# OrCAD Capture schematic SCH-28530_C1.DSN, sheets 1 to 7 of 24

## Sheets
1 01 Cover Page: title: X-T1023RDB-PC; rev: C1; company: Freescale Semiconductor; note: SCH-28530 PDF: SPF-28530; note: 6501 William Cannon Drive West; note: Austin, TX 78735-8598
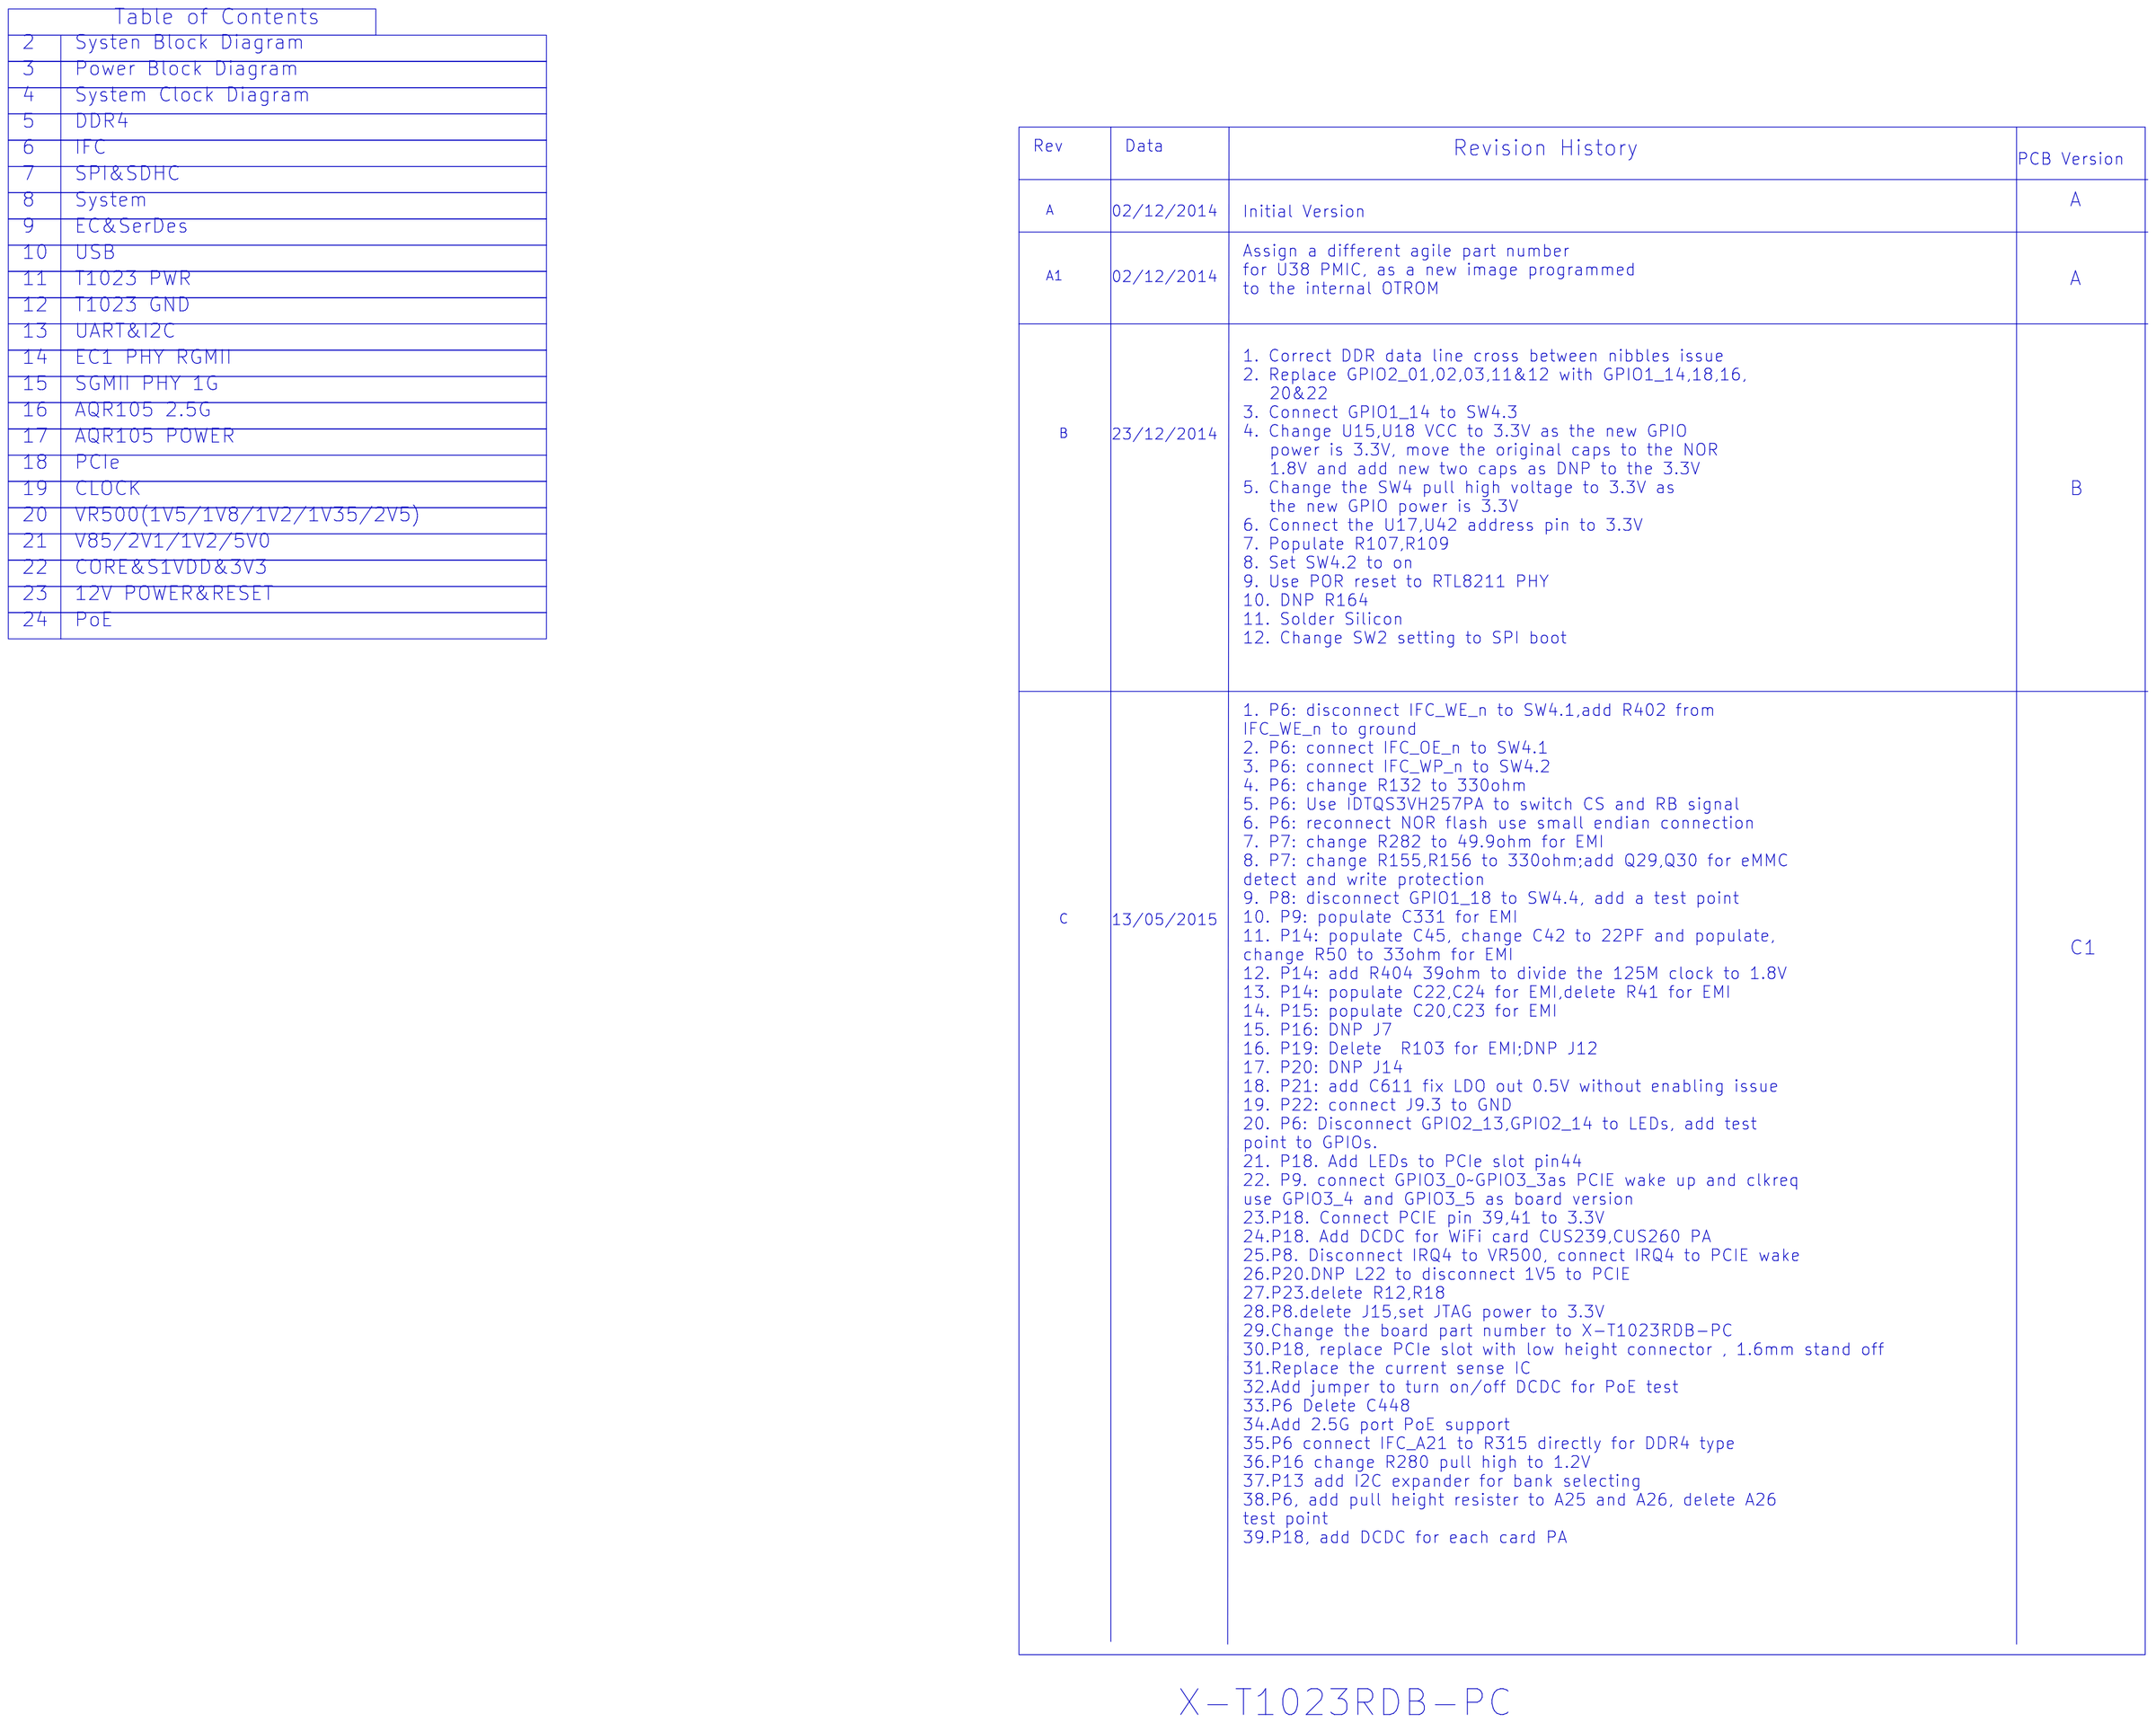
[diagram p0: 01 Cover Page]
2 02 System Block Diagram
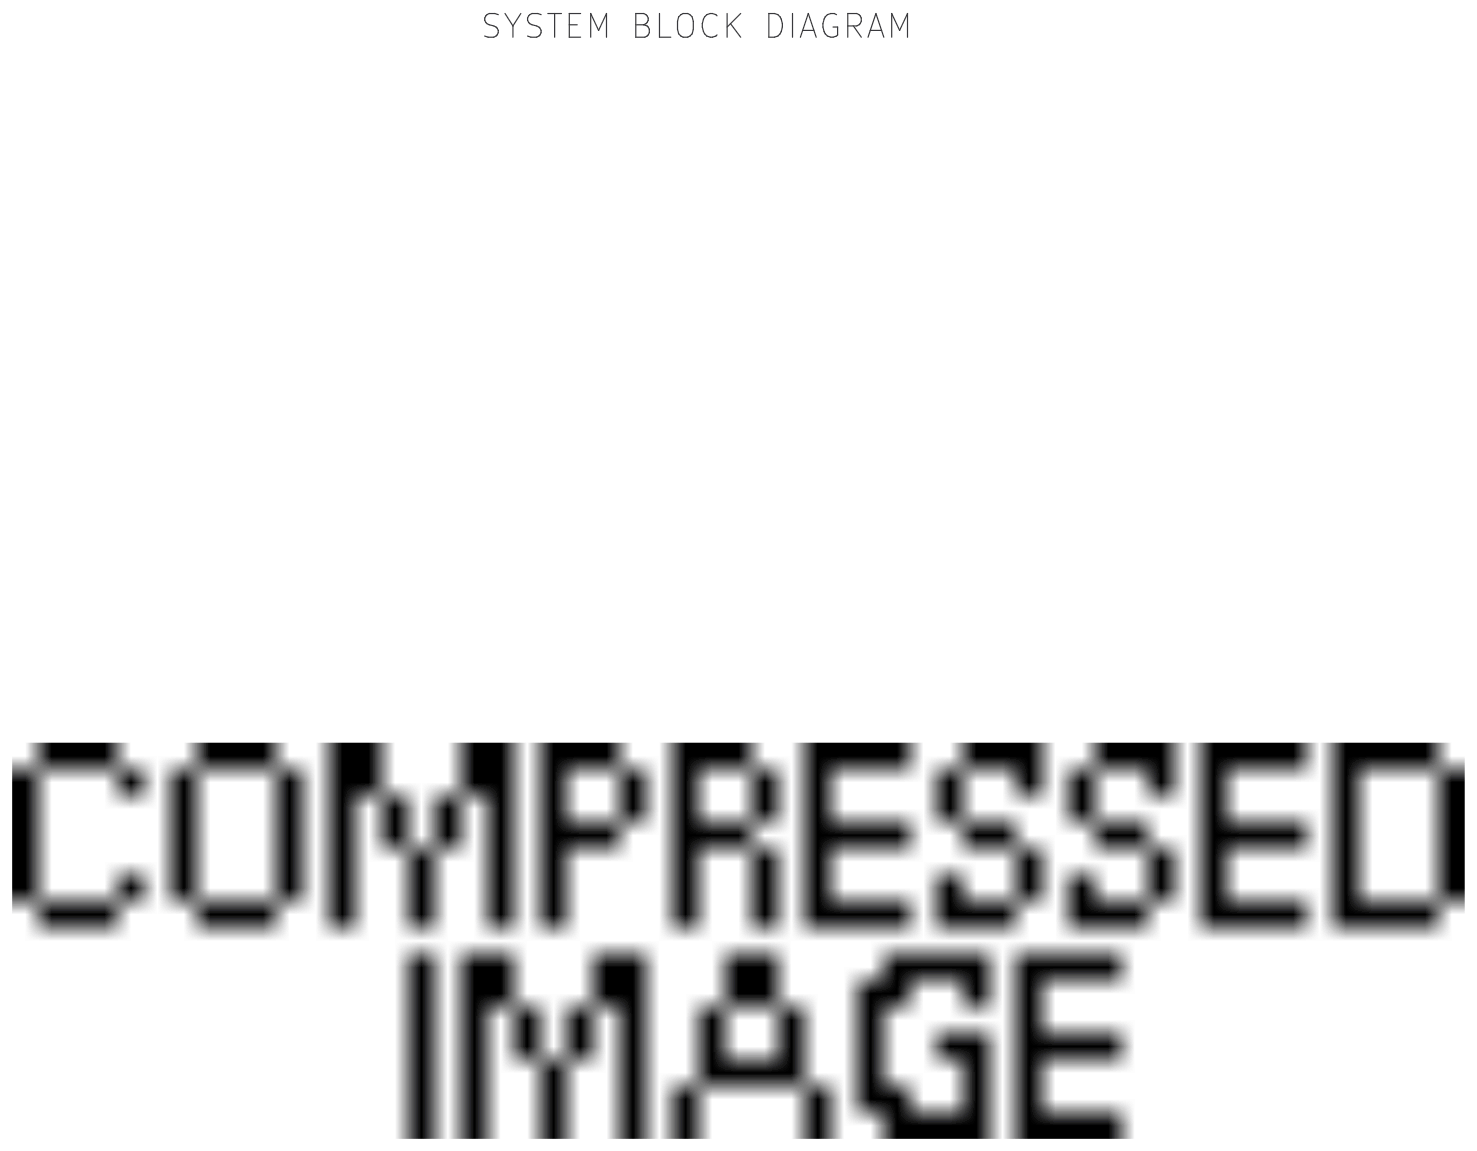
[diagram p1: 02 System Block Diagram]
3 03 Power Block Diagram
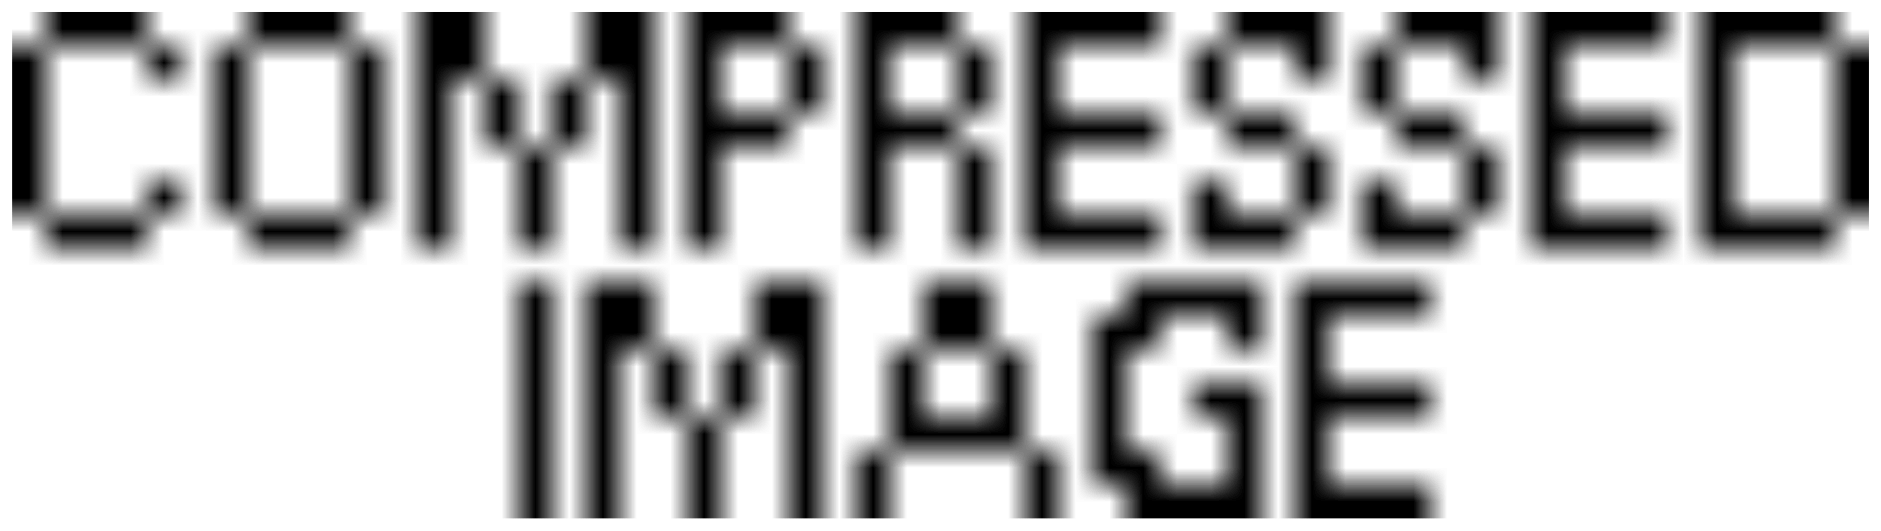
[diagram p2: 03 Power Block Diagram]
4 04 Clock Block Diagram
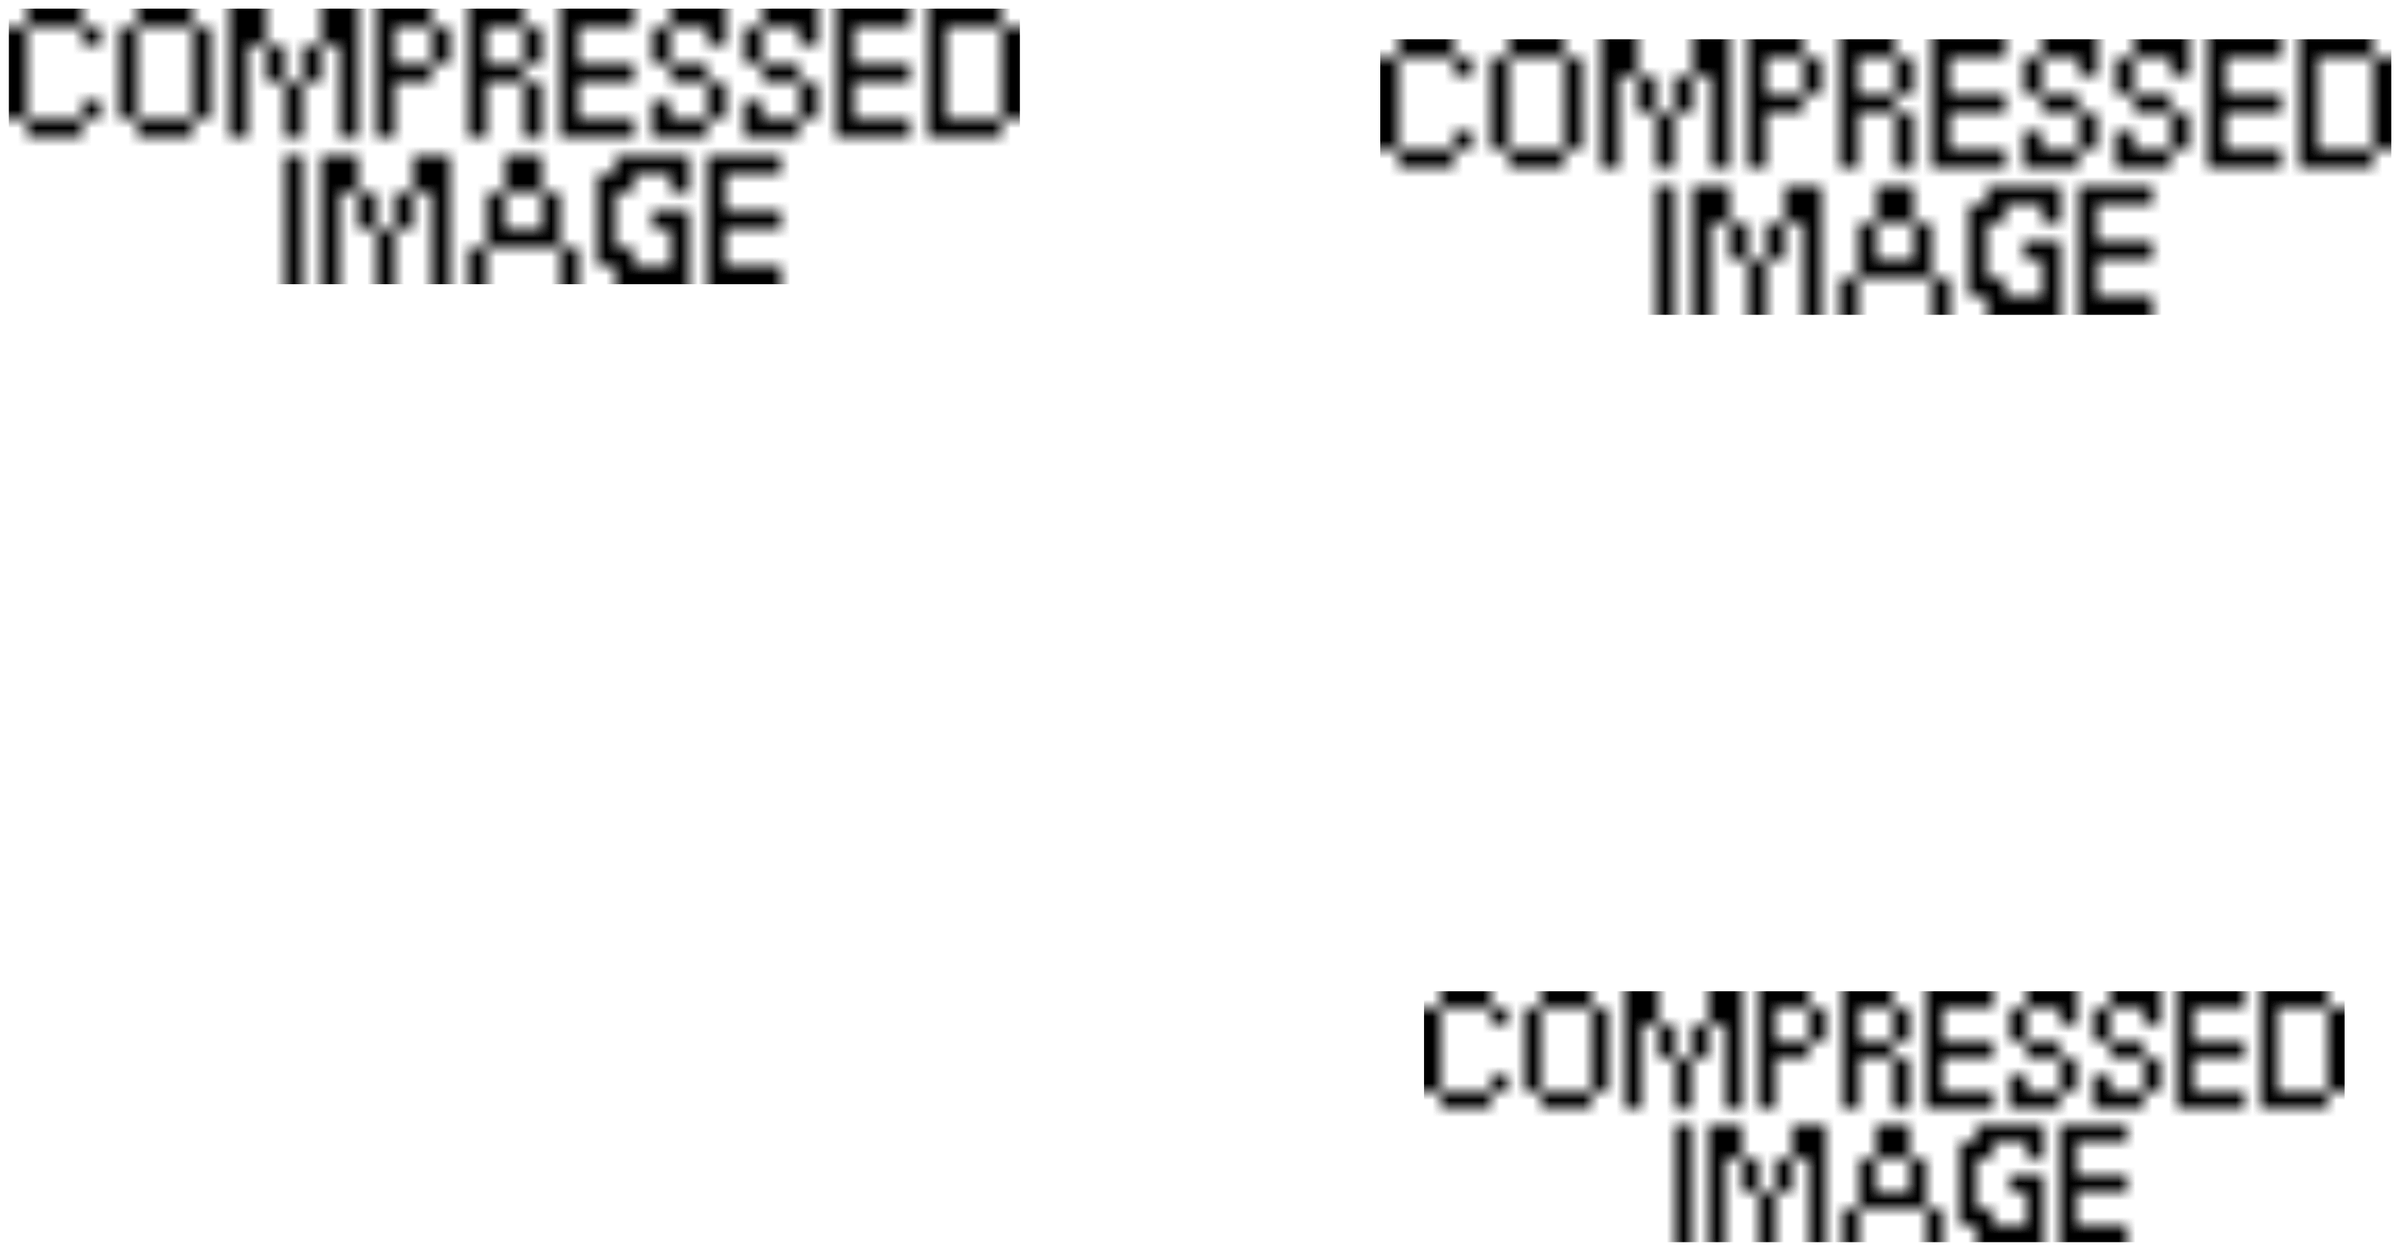
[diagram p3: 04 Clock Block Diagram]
5 05 DDR4: size C
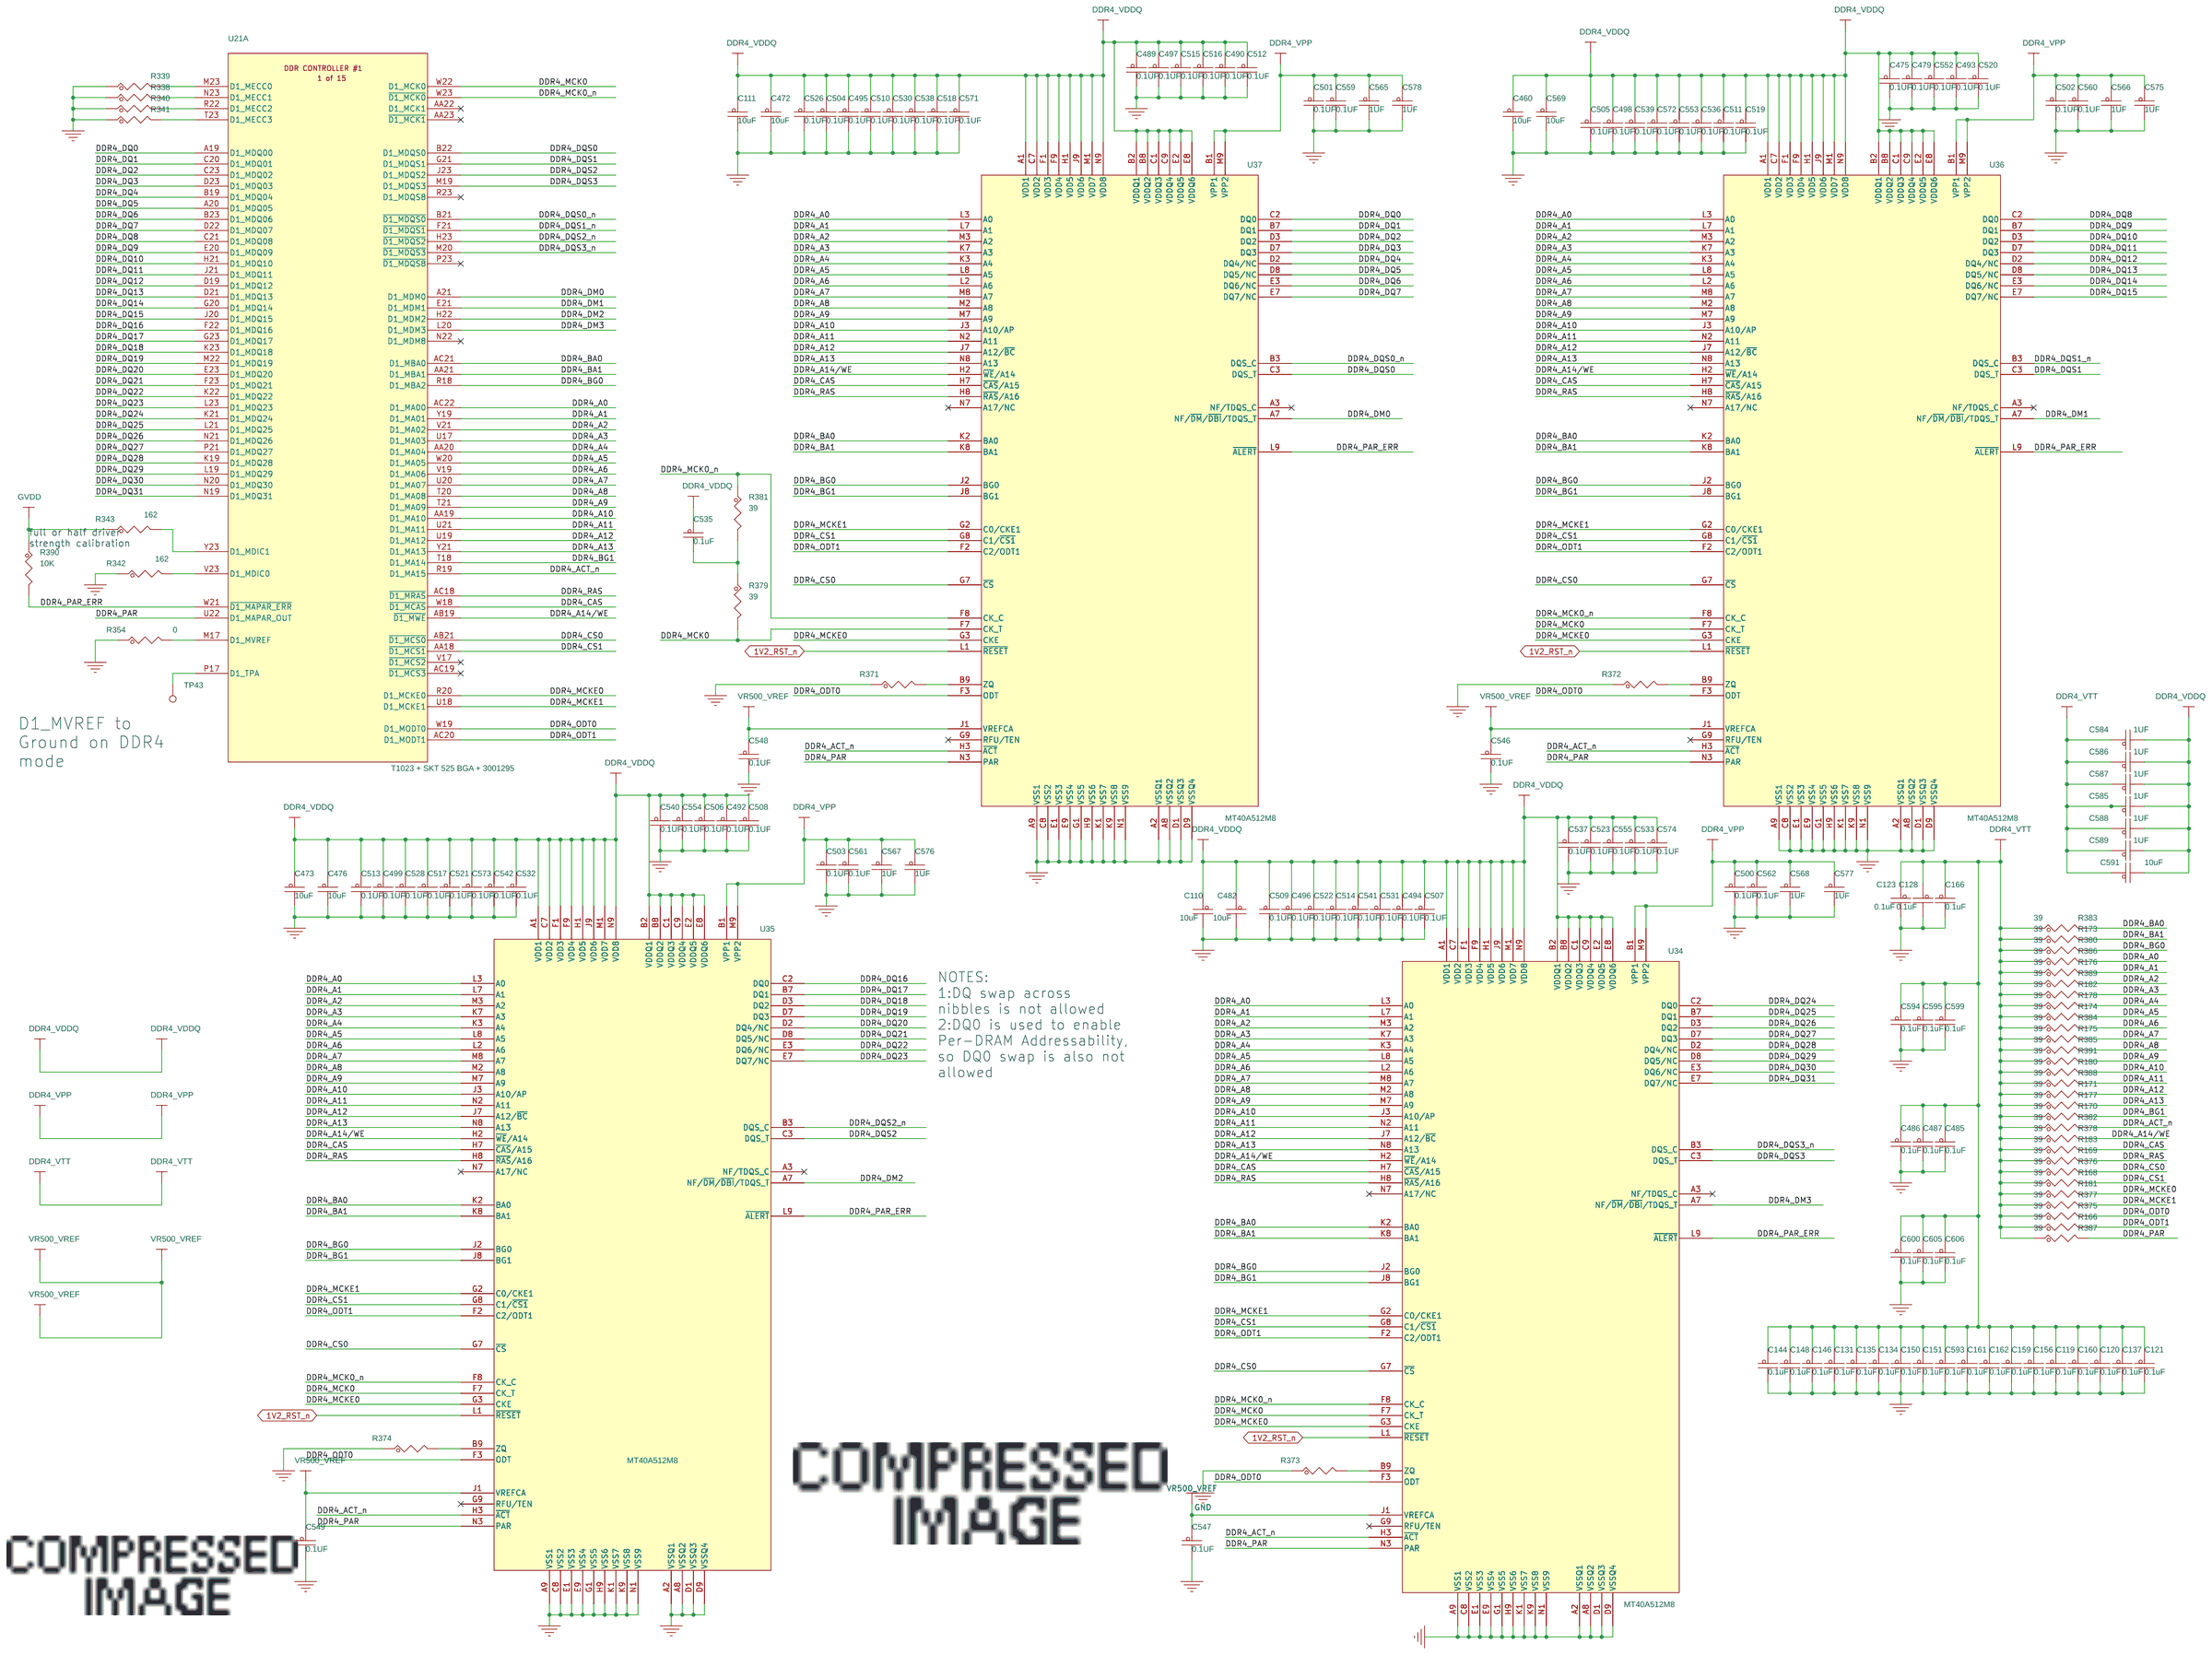
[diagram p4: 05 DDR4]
6 06 IFC: size C
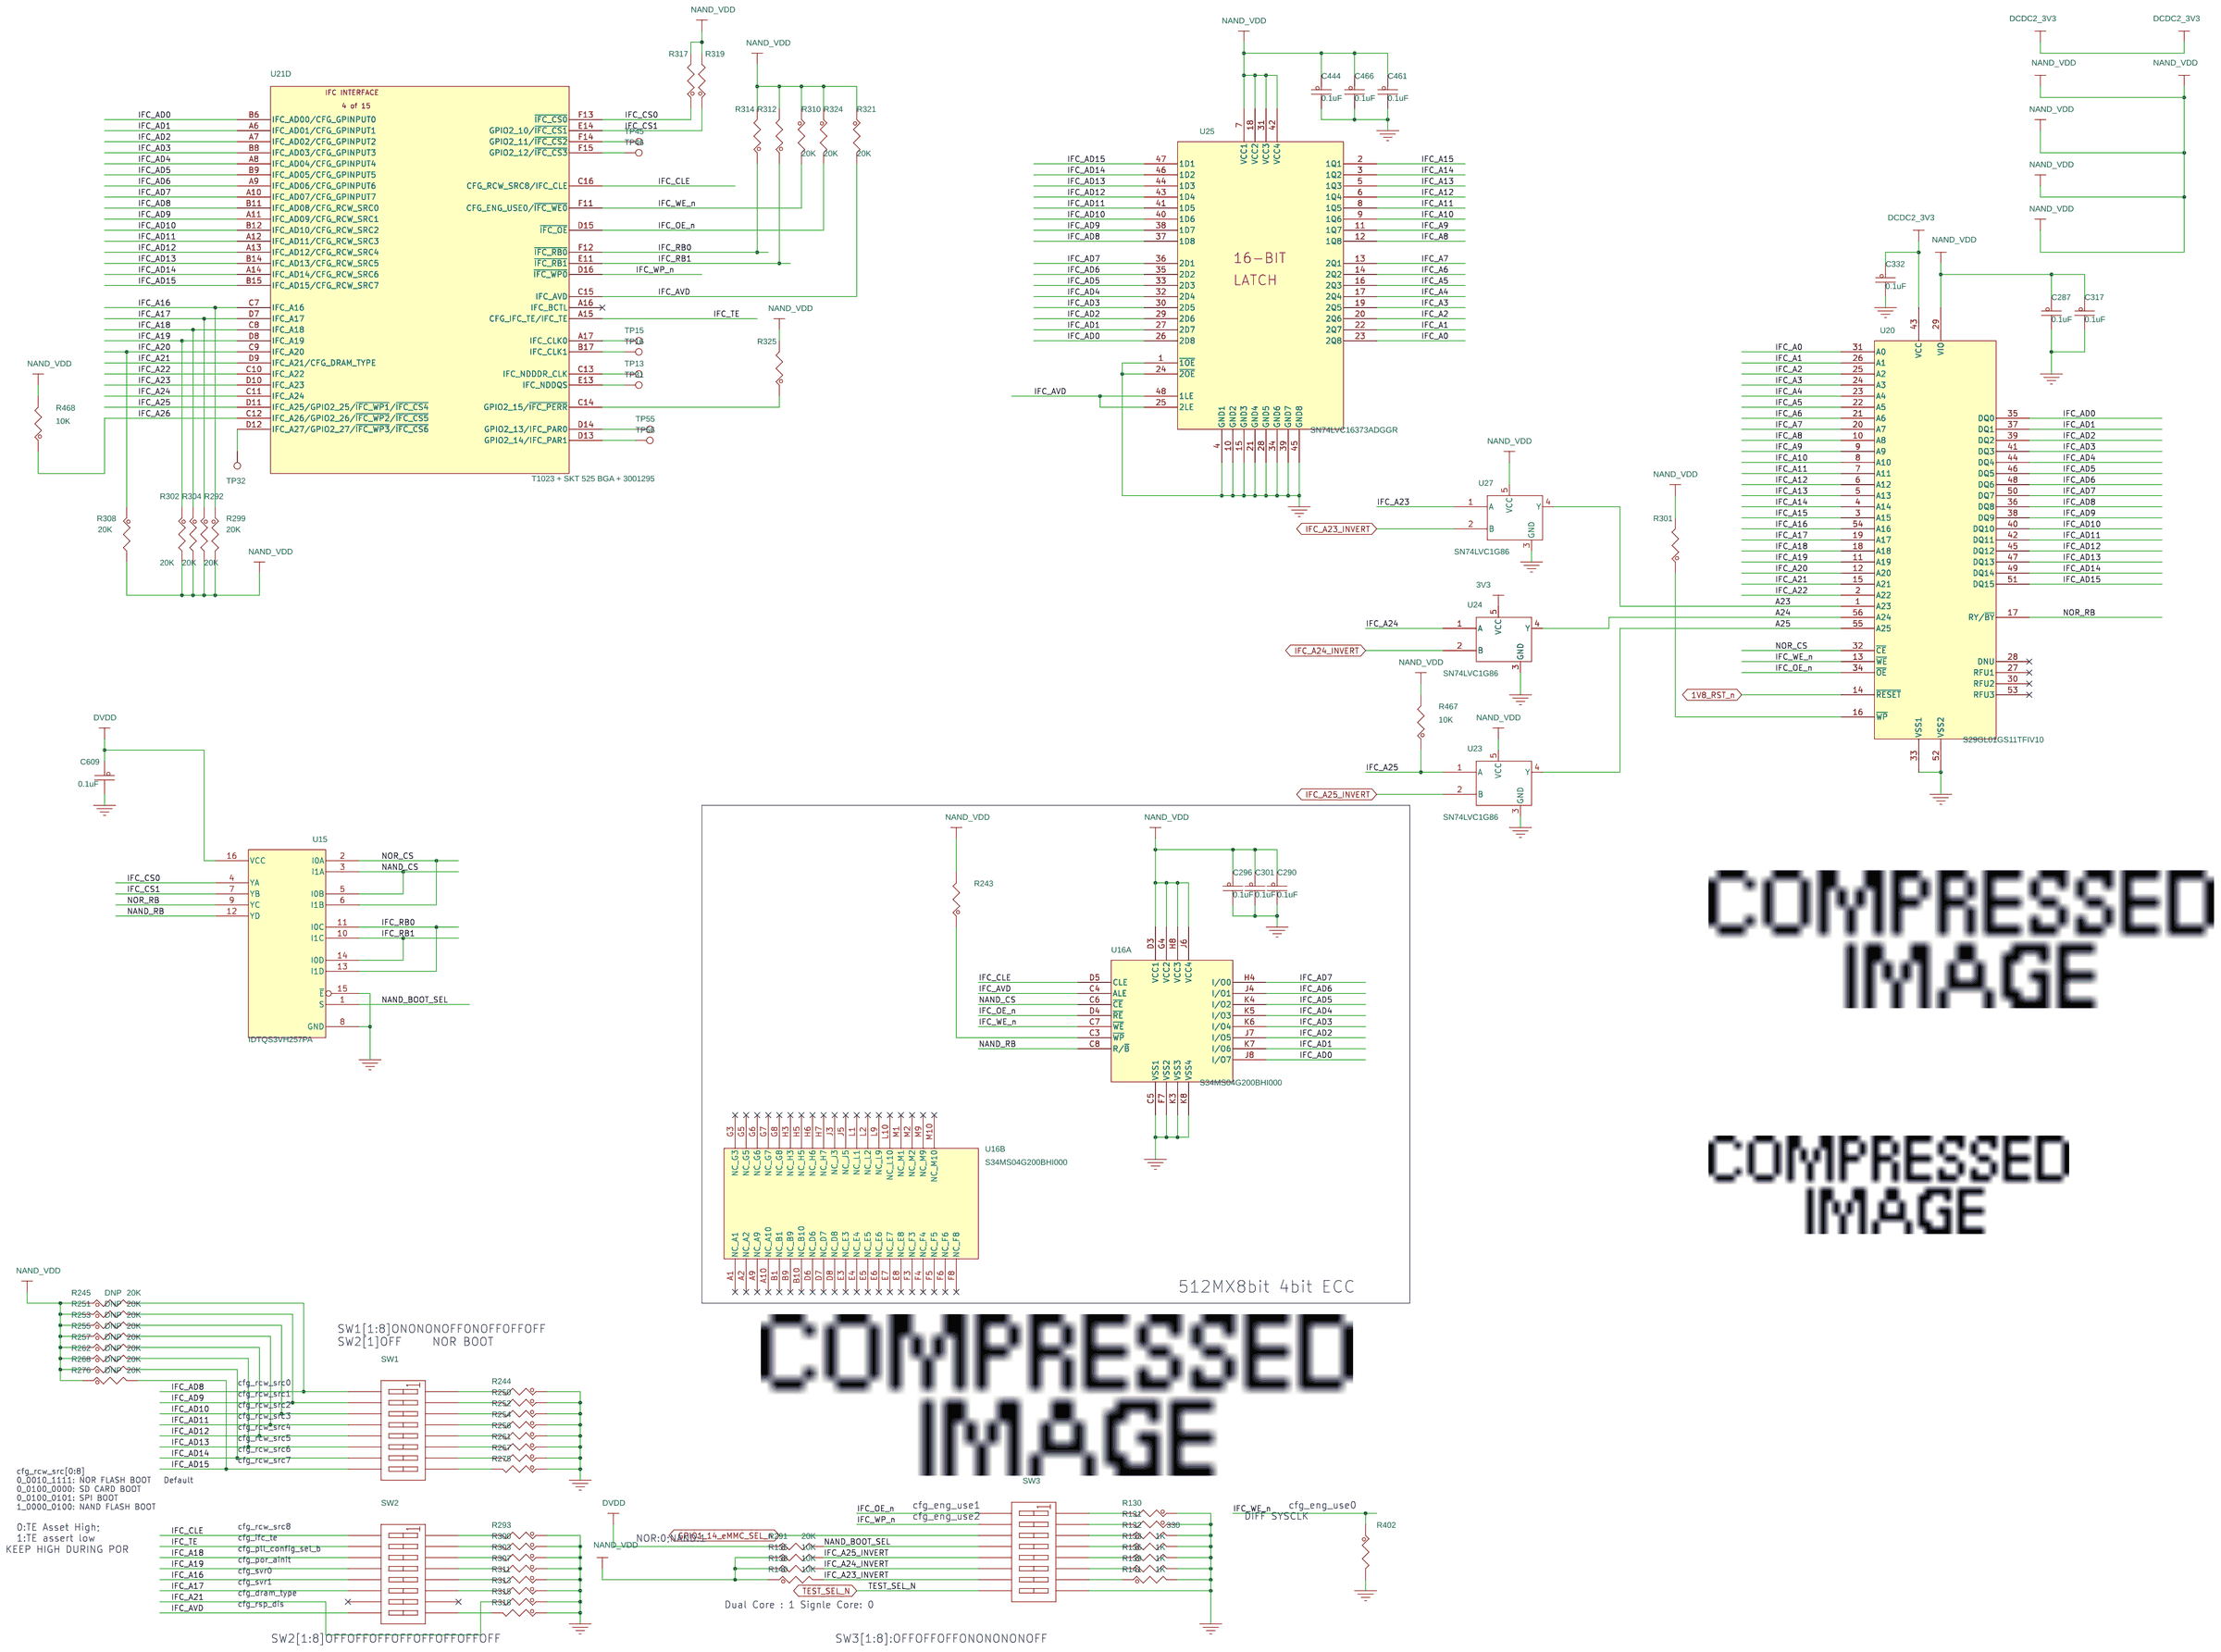
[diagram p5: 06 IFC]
7 07 SPI&SDHC: size C
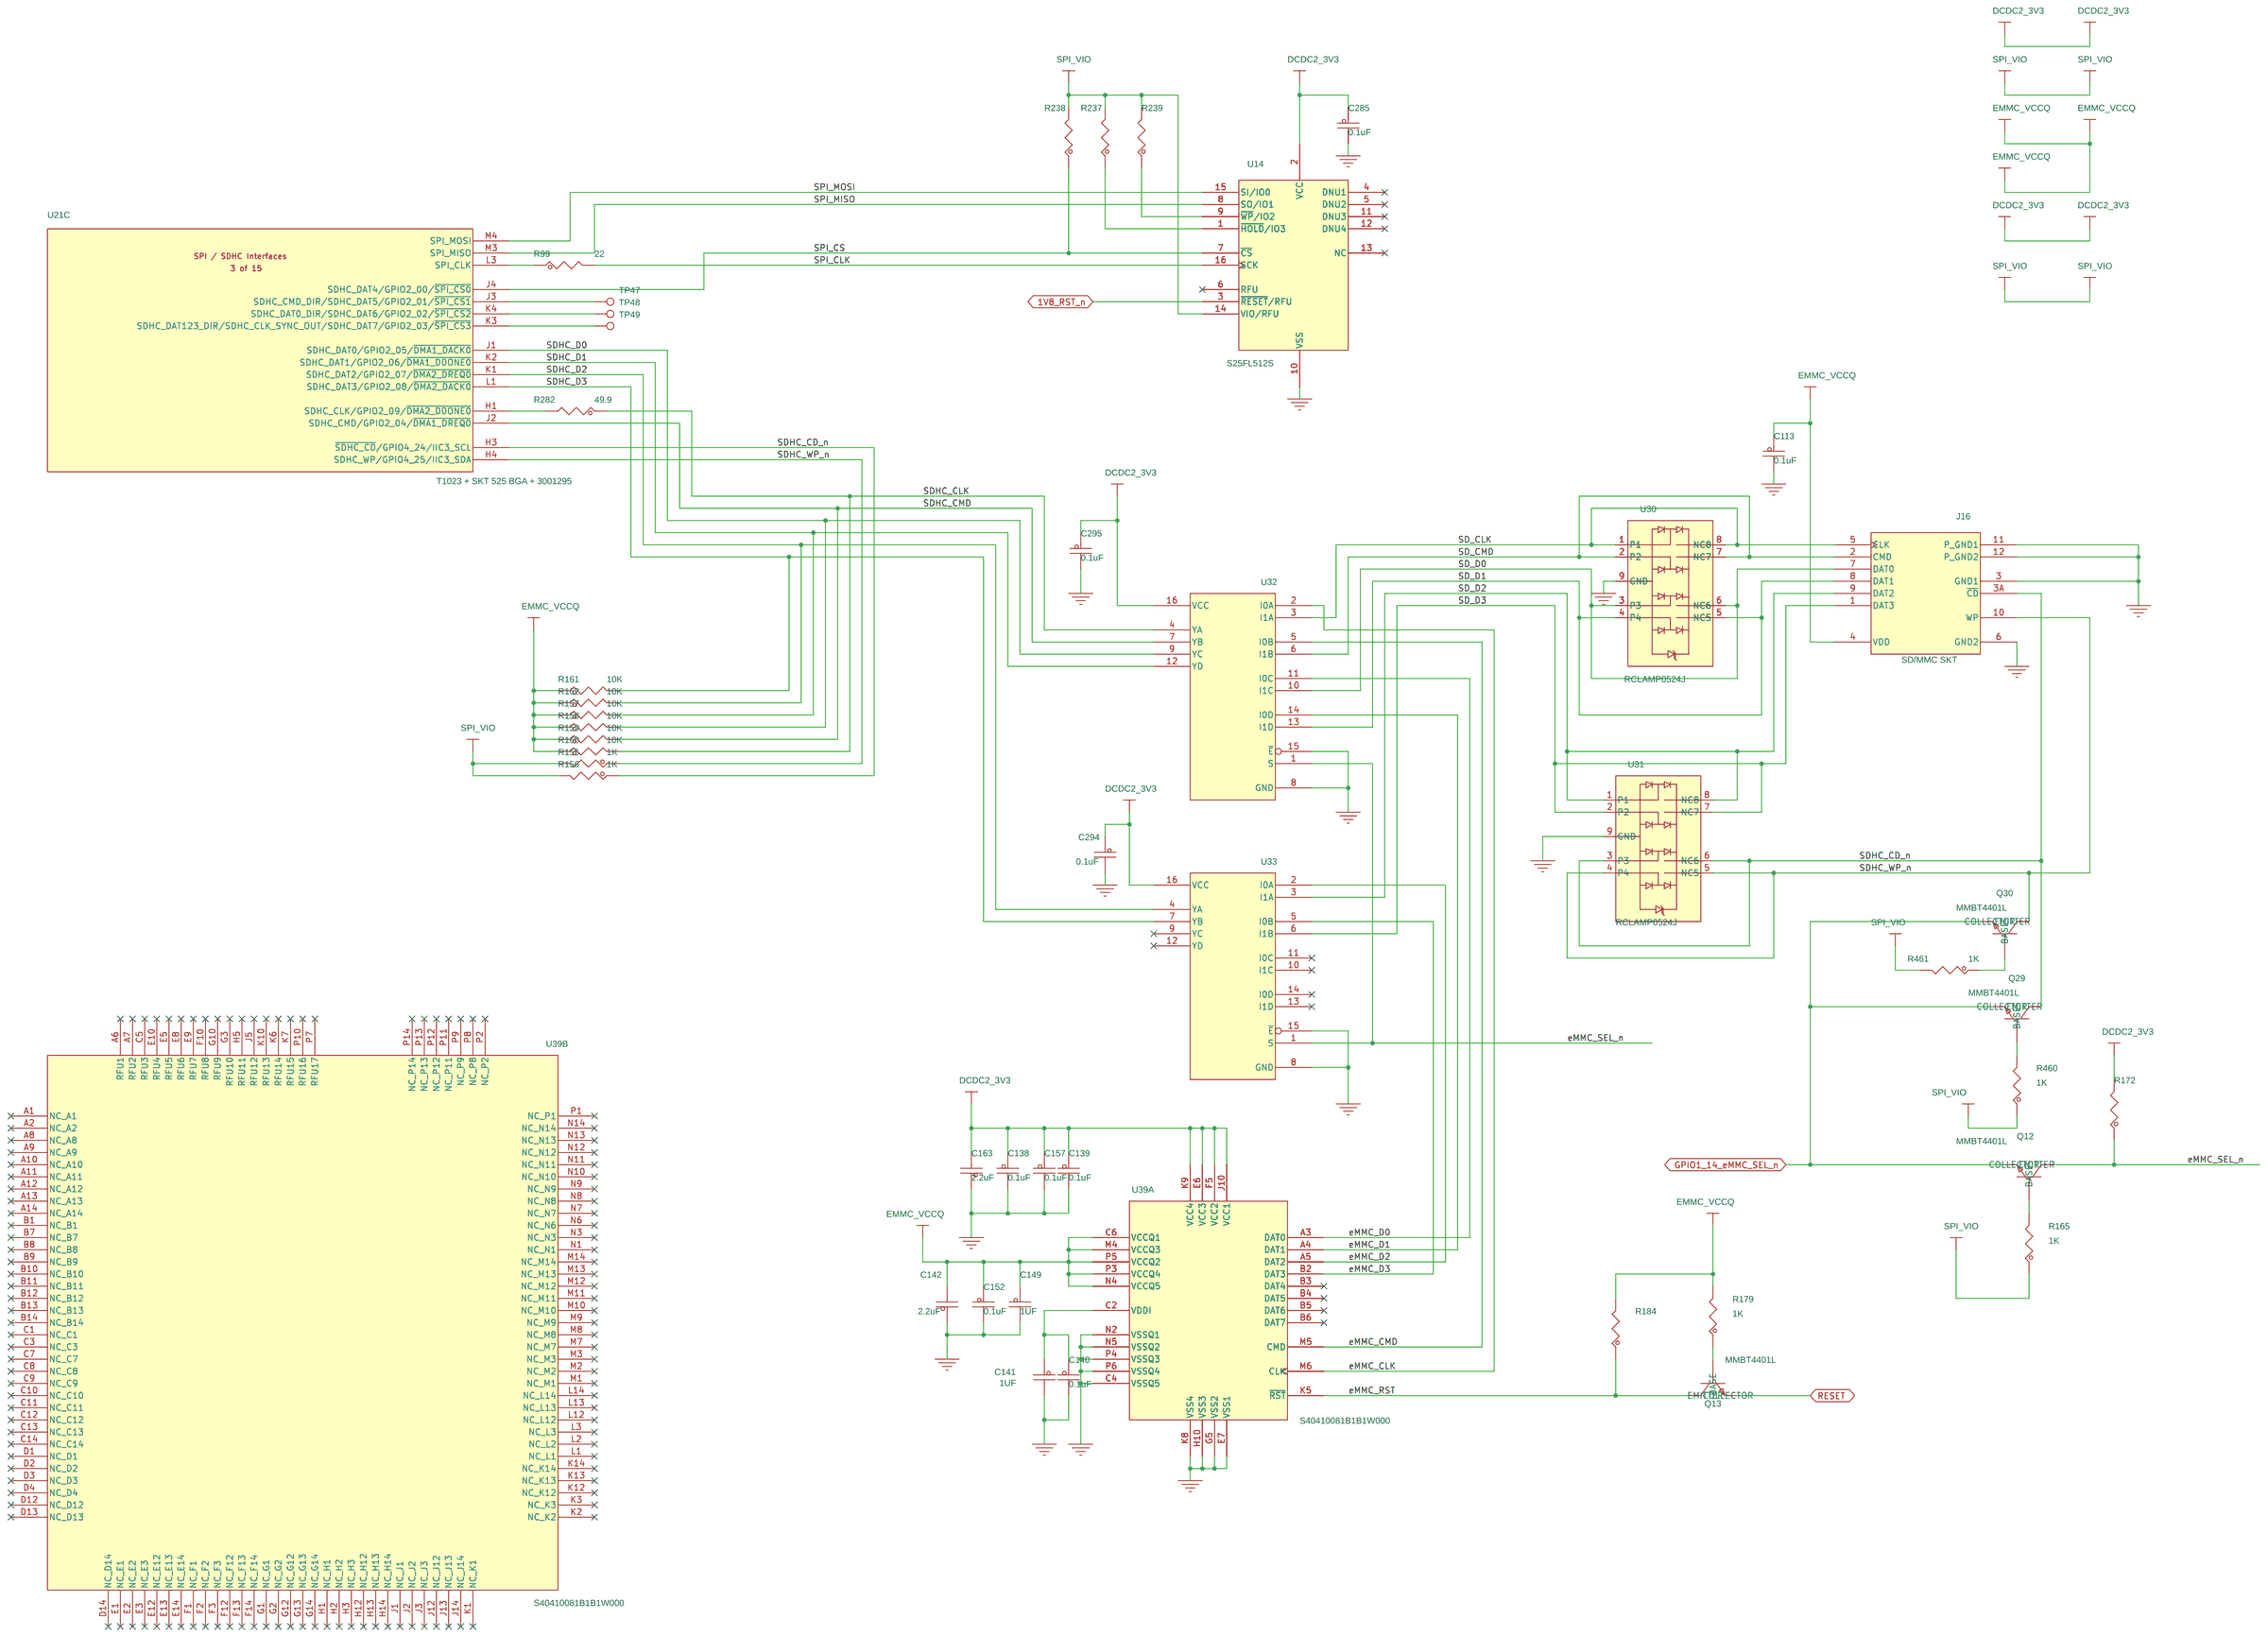
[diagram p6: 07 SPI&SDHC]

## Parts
sheet 05 DDR4
C110  10uF  [CC0603_OV]
C111  10uF  [CC0603_OV]
C119  0.1uF  [CC0402_25]
C120  0.1uF  [CC0402_25]
C121  0.1uF  [CC0402_25]
C123  0.1uF  [CC0402_25]
C128  0.1uF  [CC0402_25]
C131  0.1uF  [CC0402_25]
C134  0.1uF  [CC0402_25]
C135  0.1uF  [CC0402_25]
C137  0.1uF  [CC0402_25]
C144  0.1uF  [CC0402_25]
C146  0.1uF  [CC0402_25]
C148  0.1uF  [CC0402_25]
C150  0.1uF  [CC0402_25]
C151  0.1uF  [CC0402_25]
C156  0.1uF  [CC0402_25]
C159  0.1uF  [CC0402_25]
C160  0.1uF  [CC0402_25]
C161  0.1uF  [CC0402_25]
C162  0.1uF  [CC0402_25]
C166  0.1uF  [CC0402_25]
C460  10uF  [CC0603_OV]
C472  10uF  [CC0603_OV]
C473  10uF  [CC0603_OV]
C475  0.1UF  [CC0201]
C476  10uF  [CC0603_OV]
C479  0.1UF  [CC0201]
C482  10uF  [CC0603_OV]
C485  0.1uF  [CC0402_25]
C486  0.1uF  [CC0402_25]
C487  0.1uF  [CC0402_25]
C489  0.1UF  [CC0201]
C490  0.1UF  [CC0201]
C492  0.1UF  [CC0201]
C493  0.1UF  [CC0201]
C494  0.1UF  [CC0201]
C495  0.1UF  [CC0201]
C496  0.1UF  [CC0201]
C497  0.1UF  [CC0201]
C498  0.1UF  [CC0201]
C499  0.1UF  [CC0201]
C500  0.1UF  [CC0201]
C501  0.1UF  [CC0201]
C502  0.1UF  [CC0201]
C503  0.1UF  [CC0201]
C504  0.1UF  [CC0201]
C505  0.1UF  [CC0201]
C506  0.1UF  [CC0201]
C507  0.1UF  [CC0201]
C508  0.1UF  [CC0201]
C509  0.1UF  [CC0201]
C510  0.1UF  [CC0201]
C511  0.1UF  [CC0201]
C512  0.1UF  [CC0201]
C513  0.1UF  [CC0201]
C514  0.1UF  [CC0201]
C515  0.1UF  [CC0201]
C516  0.1UF  [CC0201]
C517  0.1UF  [CC0201]
C518  0.1UF  [CC0201]
C519  0.1UF  [CC0201]
C520  0.1UF  [CC0201]
C521  0.1UF  [CC0201]
C522  0.1UF  [CC0201]
C523  0.1UF  [CC0201]
C526  0.1UF  [CC0201]
C528  0.1UF  [CC0201]
C530  0.1UF  [CC0201]
C531  0.1UF  [CC0201]
C532  0.1UF  [CC0201]
C533  0.1UF  [CC0201]
C535  0.1uF  [CC0402_25]
C536  0.1UF  [CC0201]
C537  0.1UF  [CC0201]
C538  0.1UF  [CC0201]
C539  0.1UF  [CC0201]
C540  0.1UF  [CC0201]
C541  0.1UF  [CC0201]
C542  0.1UF  [CC0201]
C546  0.1UF  [CC0201]
C547  0.1UF  [CC0201]
C548  0.1UF  [CC0201]
C549  0.1UF  [CC0201]
C552  0.1UF  [CC0201]
C553  0.1UF  [CC0201]
C554  0.1UF  [CC0201]
C555  0.1UF  [CC0201]
C559  0.1UF  [CC0201]
C560  0.1UF  [CC0201]
C561  0.1UF  [CC0201]
C562  0.1UF  [CC0201]
C565  1UF  [CC0402_25]
C566  1UF  [CC0402_25]
C567  1UF  [CC0402_25]
C568  1UF  [CC0402_25]
C569  10uF  [CC0603_OV]
C571  0.1UF  [CC0201]
C572  0.1UF  [CC0201]
C573  0.1UF  [CC0201]
C574  0.1UF  [CC0201]
C575  1UF  [CC0402_25]
C576  1UF  [CC0402_25]
C577  1UF  [CC0402_25]
C578  1UF  [CC0402_25]
C584  1UF  [CC0402_25]
C585  1UF  [CC0402_25]
C586  1UF  [CC0402_25]
C587  1UF  [CC0402_25]
C588  1UF  [CC0402_25]
C589  1UF  [CC0402_25]
C591  10uF  [CC0603_OV]
C593  0.1uF  [CC0402_25]
C594  0.1uF  [CC0402_25]
C595  0.1uF  [CC0402_25]
C599  0.1uF  [CC0402_25]
C600  0.1uF  [CC0402_25]
C605  0.1uF  [CC0402_25]
C606  0.1uF  [CC0402_25]
R166  39  [RC0402_25]
R168  39  [RC0402_25]
R169  39  [RC0402_25]
R170  39  [RC0402_25]
R171  39  [RC0402_25]
R173  39  [RC0402_25]
R174  39  [RC0402_25]
R175  39  [RC0402_25]
R176  39  [RC0402_25]
R177  39  [RC0402_25]
R178  39  [RC0402_25]
R180  39  [RC0402_25]
R181  39  [RC0402_25]
R182  39  [RC0402_25]
R183  39  [RC0402_25]
R338  300  [RC0402_25]
R339  300  [RC0402_25]
R340  300  [RC0402_25]
R341  300  [RC0402_25]
R342  162  [RC0402_25]
R343  162  [RC0402_25]
R354  0  [RC0402_25]
R371  240  [RC0402_25]
R372  240  [RC0402_25]
R373  240  [RC0402_25]
R374  240  [RC0402_25]
R375  39  [RC0402_25]
R376  39  [RC0402_25]
R377  39  [RC0402_25]
R378  39  [RC0402_25]
R379  39  [RC0402_25]
R380  39  [RC0402_25]
R381  39  [RC0402_25]
R382  39  [RC0402_25]
R383  39  [RC0402_25]
R384  39  [RC0402_25]
R385  39  [RC0402_25]
R386  39  [RC0402_25]
R387  39  [RC0402_25]
R388  39  [RC0402_25]
R389  39  [RC0402_25]
R390  10K  [RC0603_OV]
R391  39  [RC0402_25]
TP43  35 MIL  [TESTPOINT_35MIL]
U34  MT40A512M8  [fbga78_0p8_9x11p5]
U35  MT40A512M8  [fbga78_0p8_9x11p5]
U36  MT40A512M8  [fbga78_0p8_9x11p5]
U37  MT40A512M8  [fbga78_0p8_9x11p5]
sheet 06 IFC
C287  0.1uF  [CC0402_25]
C290  0.1uF  [CC0402_25]
C296  0.1uF  [CC0402_25]
C301  0.1uF  [CC0402_25]
C317  0.1uF  [CC0402_25]
C332  0.1uF  [CC0402_25]
C444  0.1uF  [CC0402_25]
C461  0.1uF  [CC0402_25]
C466  0.1uF  [CC0402_25]
C609  0.1uF  [CC0402_25]
R130  4.7K  [RC0402_25]
R131  4.7K  [RC0402_25]
R132  330  [RC0603_OV]
R133  1K  [RC0603_OV]
R135  10K  [RC0603_OV]
R136  1K  [RC0603_OV]
R138  10K  [RC0603_OV]
R139  1K  [RC0603_OV]
R140  10K  [RC0603_OV]
R141  1K  [RC0603_OV]
R243  4.7K  [RC0402_25]
R244  4.7K  [RC0402_25]
R245  20K  [RC0402_25]
R250  4.7K  [RC0402_25]
R251  20K  [RC0402_25]
R252  4.7K  [RC0402_25]
R253  20K  [RC0402_25]
R254  4.7K  [RC0402_25]
R255  20K  [RC0402_25]
R256  4.7K  [RC0402_25]
R257  20K  [RC0402_25]
R261  4.7K  [RC0402_25]
R262  20K  [RC0402_25]
R267  4.7K  [RC0402_25]
R268  20K  [RC0402_25]
R275  4.7K  [RC0402_25]
R276  20K  [RC0402_25]
R291  20K  [RC0402_25]
R292  20K  [RC0402_25]
R293  4.7K  [RC0402_25]
R299  20K  [RC0402_25]
R300  4.7K  [RC0402_25]
R301  4.7K  [RC0402_25]
R302  20K  [RC0402_25]
R303  4.7K  [RC0402_25]
R304  20K  [RC0402_25]
R307  4.7K  [RC0402_25]
R308  20K  [RC0402_25]
R310  20K  [RC0402_25]
R311  4.7K  [RC0402_25]
R312  4.7K  [RC0402_25]
R313  4.7K  [RC0402_25]
R314  4.7K  [RC0402_25]
R315  4.7K  [RC0402_25]
R317  4.7K  [RC0402_25]
R318  4.7K  [RC0402_25]
R319  4.7K  [RC0402_25]
R321  20K  [RC0402_25]
R324  20K  [RC0402_25]
R325  4.7K  [RC0402_25]
R402  4.7K  [RC0402_25]
R467  10K  [RC0603_OV]
R468  10K  [RC0603_OV]
SW1  218-8LPST  [SW_DIP16_8POS_SM]
SW2  218-8LPST  [SW_DIP16_8POS_SM]
SW3  218-8LPST  [SW_DIP16_8POS_SM]
TP13  35 MIL  [TESTPOINT_35MIL]
TP15  35 MIL  [TESTPOINT_35MIL]
TP16  35 MIL  [TESTPOINT_35MIL]
TP31  35 MIL  [TESTPOINT_35MIL]
TP32  35 MIL  [TESTPOINT_35MIL]
TP45  35 MIL  [TESTPOINT_35MIL]
TP46  35 MIL  [TESTPOINT_35MIL]
TP55  35 MIL  [TESTPOINT_35MIL]
TP56  35 MIL  [TESTPOINT_35MIL]
U15  IDTQS3VH257PA  [TSSOP16]
U16  S34MS04G200BHI000  [vfbga63_0p8_9x11]  (sections A,B)
U20  S29GL01GS11TFIV10  [tsop56_0p5_18_4x14_in]
U23  SN74LVC1G86  [SOT-23-5]
U24  SN74LVC1G86  [SOT-23-5]
U25  SN74LVC16373ADGGR  [tssop48-11x70]
U27  SN74LVC1G86  [SOT-23-5]
sheet 07 SPI&SDHC
C113  0.1uF  [CC0402_25]
C138  0.1uF  [CC0402_25]
C139  0.1uF  [CC0402_25]
C140  0.1uF  [CC0402_25]
C141  1UF  [CC0402_25]
C142  2.2uF  [CC0402_25]
C149  1UF  [CC0402_25]
C152  0.1uF  [CC0402_25]
C157  0.1uF  [CC0402_25]
C163  2.2uF  [CC0402_25]
C285  0.1uF  [CC0402_25]
C294  0.1uF  [CC0402_25]
C295  0.1uF  [CC0402_25]
J16  SD/MMC SKT  [con_sdcard_13f_sm_ra_511]
Q12  MMBT4401L  [SOT23]
Q13  MMBT4401L  [SOT23]
Q29  MMBT4401L  [SOT23]
Q30  MMBT4401L  [SOT23]
R99  22  [RC0603_OV]
R155  1K  [RC0603_OV]
R156  1K  [RC0603_OV]
R157  10K  [RC0603_OV]
R158  10K  [RC0603_OV]
R159  10K  [RC0603_OV]
R160  10K  [RC0603_OV]
R161  10K  [RC0603_OV]
R162  10K  [RC0603_OV]
R165  1K  [RC0603_OV]
R172  4.7K  [RC0402_25]
R179  1K  [RC0603_OV]
R184  4.7K  [RC0402_25]
R237  4.7K  [RC0402_25]
R238  4.7K  [RC0402_25]
R239  4.7K  [RC0402_25]
R282  49.9  [RC0603_OV]
R460  1K  [RC0603_OV]
R461  1K  [RC0603_OV]
TP47  35 MIL  [TESTPOINT_35MIL]
TP48  35 MIL  [TESTPOINT_35MIL]
TP49  35 MIL  [TESTPOINT_35MIL]
U14  S25FL512S  [soic16_1p27_7p5x10p3]
U30  RCLAMP0524J  [SLP2710P8]
U31  RCLAMP0524J  [SLP2710P8]
U32  IDTQS3VH257PA  [TSSOP16]
U33  IDTQS3VH257PA  [TSSOP16]
U39  S40410081B1B1W000  [FBGA153_0P5_11P5X13]  (sections A,B)
sheet 10 USB
U21  T1023 + SKT 525 BGA + 3001295  [SKT_BGA525_0P8_58P6SQ_SM]  (sections A,B,C,D,E,F,G,H,I,J,K,L,M,N)

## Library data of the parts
C110 C111 C460 C472 C473 C476 C482 C569 C591 = CAP_NP: CAP CER 10uF 25V 20% X5R 0603; AGILE_PN: 150-79272; CAD_APPROVED: Yes; FPLIST: CC0603_OV,CC0603,0603_CC; HEIGHT: 1MM; MFG_NAME01: Murata; MFG_PN01: GRM188R61E106MA73D; ROHS: Yes; Tolerance: 20%; VOLTAGE: 25V
C113 C119-C121 C123 C128 C131 C134 C135 C137-C140 C144 C146 C148 C150-C152 C156 C157 C159-C162 C166 C285 C287 C290 C294-C296 C301 C317 C332 C444 C461 C466 C485-C487 C535 C593-C595 C599 C600 C605 C606 C609 = CAP_NP: CAP CER 0.1uF 6.3V 10% X5R 0402; AGILE_PN: 150-79388; CAD_APPROVED: Yes; FPLIST: CC0402_25,CC0402_HD,0402_CC; HEIGHT: 0.55MM; MFG_NAME01: TDK; MFG_PN01: C1005X5R0J104K050BA; ROHS: Yes; Tolerance: 10%; VOLTAGE: 6.3V
C475 C479 C489 C490 C492-C523 C526 C528 C530-C533 C536-C542 C546-C549 C552-C555 C559-C562 C571-C574 = CAP_NP: CAP CER 0.1UF 6.3V 10% X5R 0201; AGILE_PN: 150-75429; CAD_APPROVED: Yes; FPLIST: CC0201,CC0201_HD,CC0201_3PIN,0201_CC; HEIGHT: 0.33MM; MFG_NAME01: MURATA; MFG_PN01: GRM033R60J104KE19D; ROHS: Yes; Tolerance: 10%; VOLTAGE: 6.3V
C141 C149 C565-C568 C575-C578 C584-C589 = CAP_NP: CAP CER 1UF 6.3V 20% X5R 0402; AGILE_PN: 150-78002; CAD_APPROVED: Yes; FPLIST: CC0402_25,CC0402_HD,0402_CC; HEIGHT: 0.55MM; MFG_NAME01: MURATA; MFG_PN01: GRM155R60J105ME19D; ROHS: Yes; Tolerance: 20%; VOLTAGE: 6.3V
R166 R168-R171 R173-R178 R180-R183 R375-R389 R391 = RES: RES MF 39 OHM 1/16W 1% 0402; AGILE_PN: 470-30699; CAD_APPROVED: Yes; FPLIST: RC0402_25,RC0402_HD,0402_CC; HEIGHT: 0.40 MM; MFG_NAME01: KOA SPEER; MFG_PN01: RK73H1ETTP39R0F; ROHS: Yes; Tolerance: 1%
R338-R341 = RES: RES MF 300 OHM 1/16W 1% 0402; AGILE_PN: 470-76486; CAD_APPROVED: Yes; FPLIST: RC0402_25,RC0402_HD,0402_CC; HEIGHT: 0.4MM; MFG_NAME01: THYE MING TECH CO LTD; MFG_PN01: CR02FL6--300R; ROHS: Yes; SIGNAL_MODEL: DEFAULT_RESISTOR_330OHM_2_1; Tolerance: 1%
R342 R343 = RES: RES MF 162 OHM 1/16W 1% 0402; AGILE_PN: 470-30760; CAD_APPROVED: Yes; FPLIST: RC0402_25,RC0402_HD,0402_CC; HEIGHT: 0.40 MM; MFG_NAME01: KOA SPEER; MFG_PN01: RK73H1ETTP1620F; ROHS: Yes; Tolerance: 1%
R354 = RES: RES MF ZERO OHM 1/16W 5% 0402; AGILE_PN: 470-75394; CAD_APPROVED: Yes; FPLIST: RC0402_25,RC0402_HD,RC0402_X2,0402_CC; HEIGHT: 0.45 MM; MFG_NAME01: ROHM; MFG_PN01: MCR01MZPJ000; ROHS: Yes; SIGNAL_MODEL: RES_RC0402_25_DISCRETE_470-7539_0; Tolerance: 5%
R371-R374 = RES: RES MF 240 OHM 1/16W 1% 0402; AGILE_PN: 470-30776; CAD_APPROVED: Yes; FPLIST: RC0402_25,RC0402_HD,0402_CC; HEIGHT: 0.40 MM; MFG_NAME01: KOA SPEER; MFG_PN01: RK73H1ETTP2400F; ROHS: Yes; SIGNAL_MODEL: DEFAULT_RESISTOR_240OHM_2_1; Tolerance: 1%
R135 R138 R140 R157-R162 R390 R467 R468 = RES: RES MF 10K 1/10W 5% 0603; AGILE_PN: 470-75410; CAD_APPROVED: Yes; FPLIST: RC0603_OV,RC0603,0603_CC; HEIGHT: 0.55MM; MFG_NAME01: KOA SPEER; MFG_PN01: RK73B1JTTD103J; ROHS: Yes; Tolerance: 5%
TP13 TP15 TP16 TP31 TP32 TP43 TP45-TP49 TP55 TP56 = Test_pad: TEST PAD 35 MIL ROUND SMT; NO PART TO ORDER; AGILE_PN: 510-75219; CAD_APPROVED: Yes; HEIGHT: 0.1 MM; ROHS: Yes
U34-U37 = MT40A512M8: IC MEM DDR4 SDRAM 512MX8 0.937NS 1.2V FBGA78; AGILE_PN: 334-77600; CAD_APPROVED: Yes; HEIGHT: 1.2 MM; MFG_NAME01: MICRON; MFG_PN01: MT40A512M8HX-093E:A; ROHS: Yes
R130 R131 R172 R184 R237-R239 R243 R244 R250 R252 R254 R256 R261 R267 R275 R293 R300 R301 R303 R307 R311-R315 R317-R319 R325 R402 = RES: RES MF 4.7K 1/16W 5% 0402; AGILE_PN: 470-75626; CAD_APPROVED: Yes; FPLIST: RC0402_25,RC0402_HD,0402_CC; HEIGHT: 0.41mm; ICA_MFR_NAME: <ICA_MFR_NAME>; MFG_NAME01: KOA SPEER; MFG_PN01: RK73B1ETTP472J; ROHS: Yes; SIGNAL_MODEL: DEFAULT_RESISTOR_33OHM_2_1; Tolerance: 5%
R132 = RES: RES MF 330 OHM 1/10W 1% 0603; AGILE_PN: 470-75512; CAD_APPROVED: Yes; FPLIST: RC0603_OV,RC0603,0603_CC; HEIGHT: 0.55 MM; MFG_NAME01: KOA SPEER; MFG_PN01: RK73H1JTTD3300F; ROHS: Yes; Tolerance: 1%
R133 R136 R139 R141 R155 R156 R165 R179 R460 R461 = RES: RES MF 1K 1/10W 1% 0603; AGILE_PN: 470-80784; CAD_APPROVED: Yes; FPLIST: RC0603_OV,RC0603,0603_CC; HEIGHT: 0.55MM; MFG_NAME01: VIKING TECH CORPORATION; MFG_PN01: AR03FTNX1001; ROHS: Yes; Tolerance: 1%
R245 R251 R253 R255 R257 R262 R268 R276 = RES: RES MF 20K 1/16W 1% 0402; AGILE_PN: 470-76103; ASSY_OPT: DNP; CAD_APPROVED: Yes; FPLIST: RC0402_25,RC0402_HD,0402_CC; HEIGHT: 0.4MM; MFG_NAME01: WALSIN TECHNOLOGY CORP.; MFG_PN01: WR04X2002FTL; ROHS: Yes; Tolerance: 1%
R291 R292 R299 R302 R304 R308 R310 R321 R324 = RES: RES MF 20K 1/16W 1% 0402; AGILE_PN: 470-76103; CAD_APPROVED: Yes; FPLIST: RC0402_25,RC0402_HD,0402_CC; HEIGHT: 0.4MM; MFG_NAME01: WALSIN TECHNOLOGY CORP.; MFG_PN01: WR04X2002FTL; ROHS: Yes; Tolerance: 1%
SW1-SW3 = SW_DIP_8: SW SPST DIP 50V 100MA SMT; AGILE_PN: 510-30020; CAD_APPROVED: Yes; HEIGHT: 2.65MM; MFG_NAME01: CTS; ROHS: Yes
U15 U32 U33 = IDTQS3VH257_16P: IC LIN SW 2BIT:1BIT 500MHZ 2.3-3.6V TSSOP16; AGILE_PN: 312-75284; CAD_APPROVED: YES; HEIGHT: 1.2MM; MFG_NAME01: IDT; MFG_PN01: IDTQS3VH257PAG; ROHS: Yes; SIGNAL_MODEL: IDTQS3VH257_16P_TSSOP16_1_2MM_3_IDTQS3VH257PA
U16 = S34MS04G200BH_BGA63P: IC MEM NAND FLASH 512MX8 1.8V BGA63; AGILE_PN: 342-00607; CAD_APPROVED: Yes; HEIGHT: 1 MM; MFG_NAME01: SPANSION LLC; ROHS: Yes
U20 = S29GL01GS_56P: IC MEM NOR FLASH 1GBIT 110NS 2.7-3.6V TSOP56; AGILE_PN: 342-00609; CAD_APPROVED: Yes; HEIGHT: 1.2MM; MFG_NAME01: SPANSION LLC; ROHS: Yes
U23 U24 U27 = SN74LVC: IC GATE XOR 1.65-5.5V SOT23-5; AGILE_PN: 312-75582; CAD_APPROVED: Yes; HEIGHT: 1.45MM; MFG_NAME01: TEXAS INSTRUMENTS; MFG_PN01: SN74LVC1G86DBVR; ROHS: Yes
U25 = SN74LVC16373A_48P: IC D-LATCH 16BIT TS 1.65-3.6V TSSOP48; AGILE_PN: 312-80748; CAD_APPROVED: Yes; HEIGHT: 1.2MM; MFG_NAME01: TEXAS INSTRUMENTS; ROHS: Yes
C142 C163 = CAP_NP: CAP CER 2.2uF 10V 10% X5R 0402; AGILE_PN: 150-78974; CAD_APPROVED: Yes; FPLIST: CC0402_25,CC0402_HD,0402_CC; HEIGHT: 0.55 MM; MFG_NAME01: TDK; MFG_PN01: C1005X5R1A225K; ROHS: Yes; Tolerance: 10%; VOLTAGE: 10V
J16 = CONN_SDCARD_1X13_F_511: CON 9 SKT SD/MMC RA SMT REVERSED MOUNT./ EJECT SPRING 67MIL SP 2.9MM AU; AGILE_PN: 211-78806; CAD_APPROVED: Yes; HEIGHT: 3.0 MM; MFG_NAME01: Kyocera; MFG_PN01: 14 5638 109 511 859+; ROHS: Yes
Q12 Q13 Q29 Q30 = NPN: TRAN NPN SW 600MA 40V AEC-Q101 SOT23; AGILE_PN: 480-75087; CAD_APPROVED: Yes; HEIGHT: 1.11MM; MFG_NAME01: ON SEMICONDUCTOR; MFG_PN01: MMBT4401LT1G; ROHS: Yes
R99 = RES: RES MF 22.0 OHM 1/10W 1% 0603; AGILE_PN: 470-75425; CAD_APPROVED: Yes; FPLIST: RC0603_OV,RC0603,0603_CC; HEIGHT: 0.6MM; MFG_NAME01: KOA SPEER; MFG_PN01: RK73H1JTTD22R0F; ROHS: Yes; Tolerance: 1%
R282 = RES: RES MF 49.9 OHM 1/10W 1% 0603; AGILE_PN: 470-75432; CAD_APPROVED: Yes; FPLIST: RC0603_OV,RC0603,0603_CC; HEIGHT: 0.55 MM; MFG_NAME01: KOA SPEER; MFG_PN01: RK73H1JTTD49R9F; ROHS: Yes; Tolerance: 1%
U14 = S25FL256S_SOIC_16P: IC MEM FLASH 512MBIT 133MHz 2.7-3.6V SOIC16; AGILE_PN: 342-00598; CAD_APPROVED: Yes; HEIGHT: 2.65 MM; MFG_NAME01: SPANSION LLC; MFG_PN01: S25FL512SAGMFI010; ROHS: Yes
U30 U31 = RCLAMP0524J: DIODE TVS ARRAY HDMI/eSATA LEVEL LOW CAPACITANCE 5V SMD; AGILE_PN: 480-77118; CAD_APPROVED: Yes; HEIGHT: 0.65 MM; MFG_NAME01: SEMTECH CORP; MFG_PN01: RCLAMP0524J.TCT; ROHS: Yes
U39 = S40410161B1_FBGA_153P: IC MEM FLASH 8GB EMMC 4.51 CTLER 200MHZ 2.7-3.6V FBGA153; AGILE_PN: TMP-WF-23144; CAD_APPROVED: Yes; HEIGHT: 1 MM; MFG_NAME01: SPANSION LLC; PRE_APN: 342-00605; ROHS: Yes
U21 = T1023_BGA_525P: SUBASSEMBLY IC MPU T1023 POWERPC QORIQ 1V 1.2GHZ FCPBGA525 + SKT 525 BGA SMT 0.8MM 90H -- + HEATSINK; AGILE_PN: 750-77603; CAD_APPROVED: Yes; HEIGHT: 33.2MM; MFG_NAME01: Subassembly; MFG_PN01: 211-79483,330-76995,901-76858; ROHS: Yes; FPLIST: SKT_BGA525_0P8_58P6SQ_SM,skt_bga525_0p8mm_59x59_NSP

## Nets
1V2_RST_n: U34.L1(~{RESET}) U35.L1(~{RESET}) U36.L1(~{RESET}) U37.L1(~{RESET}) ; also on sheet 16 21
1V8_RST_n: U14.3(~{RESET}/RFU) U20.14(~{RESET}) ; also on sheet 21
AVDD_CGA1: C287.1 C290.1 C296.1 C301.1 C317.1 C444.1 C461.1 C466.1 R135.1 R138.1 R140.1 R155.2 R156.2 R165.1 R237.2 R238.2 R239.2 R243.2 R245.1 R251.1 R253.1 R255.1 R257.1 R262.1 R268.1 R276.1 R292.2 R299.2 R301.2 R302.2 R304.2 R308.2 R310.1 R312.2 R314.2 R317.2 R319.2 R321.1 R324.1 R325.2 R460.1 R461.2 R467.2 R468.2 U14.14(VIO/RFU) U16.D3(VCC1) U16.G4(VCC2) U16.H8(VCC3) U16.J6(VCC4) U20.29(VIO) U23.5(VCC) U24.5(VCC) U25.7(VCC1) U25.18(VCC2) U25.31(VCC3) U25.42(VCC4) U27.5(VCC) ; also on sheet 8 9 11 12 13 20 21 24
GND: C110.2 C111.2 C113.2 C119.2 C120.2 C121.2 C123.2 C128.2 C131.2 C134.2 C135.2 C137.2 C138.2 C139.2 C140.2 C141.2 C142.1 C144.2 C146.2 C148.2 C149.2 C150.2 C151.2 C152.2 C156.2 C157.2 C159.2 C160.2 C161.2 C162.2 C163.1 C166.2 C285.2 C287.2 C290.2 C294.2 C295.2 C296.2 C301.2 C317.2 C332.2 C444.2 C460.2 C461.2 C466.2 C472.2 C473.2 C475.2 C476.2 C479.2 C482.2 C485.2 C486.2 C487.2 C489.2 C490.2 C492.2 C493.2 C494.2 C495.2 C496.2 C497.2 C498.2 C499.2 C500.2 C501.2 C502.2 C503.2 C504.2 C505.2 C506.2 C507.2 C508.2 C509.2 C510.2 C511.2 C512.2 C513.2 C514.2 C515.2 C516.2 C517.2 C518.2 C519.2 C520.2 C521.2 C522.2 C523.2 C526.2 C528.2 C530.2 C531.2 C532.2 C533.2 C536.2 C537.2 C538.2 C539.2 C540.2 C541.2 C542.2 C546.2 C547.2 C548.2 C549.2 C552.2 C553.2 C554.2 C555.2 C559.2 C560.2 C561.2 C562.2 C565.2 C566.2 C567.2 C568.2 C569.2 C571.2 C572.2 C573.2 C574.2 C575.2 C576.2 C577.2 C578.2 C593.2 C594.2 C595.2 C599.2 C600.2 C605.2 C606.2 C609.2 J16.3(GND1) J16.6(GND2) J16.11(P_GND1) J16.12(P_GND2) R130.1 R131.1 R132.2 R133.2 R136.2 R139.2 R141.2 R244.1 R250.1 R252.1 R254.1 R256.1 R261.1 R267.1 R275.1 R293.1 R300.1 R303.1 R307.1 R311.1 R313.1 R315.1 R318.1 R338.1 R339.1 R340.1 R341.1 R342.1 R354.1 R371.1 R372.1 R373.1 R374.1 R402.2 SW3.9 U14.10(VSS) U15.8(GND) U15.15(~{E}) U16.C5(VSS1) U16.F7(VSS2) U16.K3(VSS3) U16.K8(VSS4) U20.33(VSS1) U20.52(VSS2) U23.3(GND) U24.3(GND) U25.1(~{1OE}) U25.4(GND1) U25.10(GND2) U25.15(GND3) U25.21(GND4) U25.24(~{2OE}) U25.28(GND5) U25.34(GND6) U25.39(GND7) U25.45(GND8) U27.3(GND) U30.9(GND) U31.9(GND) U32.8(GND) U32.15(~{E}) U33.8(GND) U33.15(~{E}) U34.A2(VSSQ1) U34.A8(VSSQ2) U34.A9(VSS1) U34.C8(VSS2) U34.D1(VSSQ3) U34.D9(VSSQ4) U34.E1(VSS3) U34.E9(VSS4) U34.G1(VSS5) U34.H9(VSS6) U34.K1(VSS7) U34.K9(VSS8) U34.N1(VSS9) U35.A2(VSSQ1) U35.A8(VSSQ2) U35.A9(VSS1) U35.C8(VSS2) U35.D1(VSSQ3) U35.D9(VSSQ4) U35.E1(VSS3) U35.E9(VSS4) U35.G1(VSS5) U35.H9(VSS6) U35.K1(VSS7) U35.K9(VSS8) U35.N1(VSS9) U36.A2(VSSQ1) U36.A8(VSSQ2) U36.A9(VSS1) U36.C8(VSS2) U36.D1(VSSQ3) U36.D9(VSSQ4) U36.E1(VSS3) U36.E9(VSS4) U36.G1(VSS5) U36.H9(VSS6) U36.K1(VSS7) U36.K9(VSS8) U36.N1(VSS9) U37.A2(VSSQ1) U37.A8(VSSQ2) U37.A9(VSS1) U37.C8(VSS2) U37.D1(VSSQ3) U37.D9(VSSQ4) U37.E1(VSS3) U37.E9(VSS4) U37.G1(VSS5) U37.H9(VSS6) U37.K1(VSS7) U37.K9(VSS8) U37.N1(VSS9) U39.C4(VSSQ5) U39.E7(VSS1) U39.G5(VSS2) U39.H10(VSS3) U39.K8(VSS4) U39.N2(VSSQ1) U39.N5(VSSQ2) U39.P4(VSSQ3) U39.P6(VSSQ4) ; also on sheet 8 9 10 11 12 13 14 15 16 17 18 19 20 21 22 23 24
A23: U20.1(A23) U27.4(Y)
A24: U20.56(A24) U24.4(Y)
A25: U20.55(A25) U23.4(Y)
AQR105_FLASH: C500.1 C501.1 C502.1 C503.1 C559.1 C560.1 C561.1 C562.1 C565.1 C566.1 C567.1 C568.1 C575.1 C576.1 C577.1 C578.1 U34.B1(VPP1) U34.M9(VPP2) U35.B1(VPP1) U35.M9(VPP2) U36.B1(VPP1) U36.M9(VPP2) U37.B1(VPP1) U37.M9(VPP2) ; also on sheet 16 17 24
D1_MVREF: C546.1 C547.1 C548.1 C549.1 U34.J1(VREFCA) U35.J1(VREFCA) U36.J1(VREFCA) U37.J1(VREFCA) ; also on sheet 24
DCDC2_3V3: C138.1 C139.1 C157.1 C163.2 C285.1 C294.1 C295.1 C332.1 C609.1 R172.2 R291.1 U14.2(VCC) U15.16(VCC) U20.43(VCC) U32.16(VCC) U33.16(VCC) U39.E6(VCC3) U39.F5(VCC2) U39.J10(VCC1) U39.K9(VCC4) ; also on sheet 8 10 11 13 14 15 18 19 20 21 23 24
DDR4_A0: R386.2 U21.AC22(D1_MA00) U34.L3(A0) U35.L3(A0) U36.L3(A0) U37.L3(A0)
DDR4_A1: R176.2 U21.Y19(D1_MA01) U34.L7(A1) U35.L7(A1) U36.L7(A1) U37.L7(A1)
DDR4_A2: R389.2 U21.V21(D1_MA02) U34.M3(A2) U35.M3(A2) U36.M3(A2) U37.M3(A2)
DDR4_A3: R182.2 U21.U17(D1_MA03) U34.K7(A3) U35.K7(A3) U36.K7(A3) U37.K7(A3)
DDR4_A4: R178.2 U21.AA20(D1_MA04) U34.K3(A4) U35.K3(A4) U36.K3(A4) U37.K3(A4)
DDR4_A5: R174.2 U21.W20(D1_MA05) U34.L8(A5) U35.L8(A5) U36.L8(A5) U37.L8(A5)
DDR4_A6: R384.2 U21.V19(D1_MA06) U34.L2(A6) U35.L2(A6) U36.L2(A6) U37.L2(A6)
DDR4_A7: R175.2 U21.U20(D1_MA07) U34.M8(A7) U35.M8(A7) U36.M8(A7) U37.M8(A7)
DDR4_A8: R385.2 U21.T20(D1_MA08) U34.M2(A8) U35.M2(A8) U36.M2(A8) U37.M2(A8)
DDR4_A9: R391.2 U21.T21(D1_MA09) U34.M7(A9) U35.M7(A9) U36.M7(A9) U37.M7(A9)
DDR4_A10: R180.2 U21.AA19(D1_MA10) U34.J3(A10/AP) U35.J3(A10/AP) U36.J3(A10/AP) U37.J3(A10/AP)
DDR4_A11: R388.2 U21.U21(D1_MA11) U34.N2(A11) U35.N2(A11) U36.N2(A11) U37.N2(A11)
DDR4_A12: R171.2 U21.U19(D1_MA12) U34.J7(A12/~{BC}) U35.J7(A12/~{BC}) U36.J7(A12/~{BC}) U37.J7(A12/~{BC})
DDR4_A13: R177.2 U21.Y21(D1_MA13) U34.N8(A13) U35.N8(A13) U36.N8(A13) U37.N8(A13)
DDR4_A14/WE: R378.2 U21.AB19(~{D1_MWE}) U34.H2(~{WE}/A14) U35.H2(~{WE}/A14) U36.H2(~{WE}/A14) U37.H2(~{WE}/A14)
DDR4_ACT_n: R382.2 U21.R19(D1_MA15) U34.H3(~{ACT}) U35.H3(~{ACT}) U36.H3(~{ACT}) U37.H3(~{ACT})
DDR4_BA0: R383.2 U21.AC21(D1_MBA0) U34.K2(BA0) U35.K2(BA0) U36.K2(BA0) U37.K2(BA0)
DDR4_BA1: R173.2 U21.AA21(D1_MBA1) U34.K8(BA1) U35.K8(BA1) U36.K8(BA1) U37.K8(BA1)
DDR4_BG0: R380.2 U21.R18(D1_MBA2) U34.J2(BG0) U35.J2(BG0) U36.J2(BG0) U37.J2(BG0)
DDR4_BG1: R170.2 U21.T18(D1_MA14) U34.J8(BG1) U35.J8(BG1) U36.J8(BG1) U37.J8(BG1)
DDR4_CAS: R183.2 U21.W18(~{D1_MCAS}) U34.H7(~{CAS}/A15) U35.H7(~{CAS}/A15) U36.H7(~{CAS}/A15) U37.H7(~{CAS}/A15)
DDR4_CS0: R376.2 U21.AB21(~{D1_MCS0}) U34.G7(~{CS}) U35.G7(~{CS}) U36.G7(~{CS}) U37.G7(~{CS})
DDR4_CS1: R168.2 U21.AA18(~{D1_MCS1}) U34.G8(C1/~{CS1}) U35.G8(C1/~{CS1}) U36.G8(C1/~{CS1}) U37.G8(C1/~{CS1})
DDR4_DM0: U21.A21(D1_MDM0) U37.A7(NF/~{DM}/~{DBI}/TDQS_T)
DDR4_DM1: U21.E21(D1_MDM1) U36.A7(NF/~{DM}/~{DBI}/TDQS_T)
DDR4_DM2: U21.H22(D1_MDM2) U35.A7(NF/~{DM}/~{DBI}/TDQS_T)
DDR4_DM3: U21.L20(D1_MDM3) U34.A7(NF/~{DM}/~{DBI}/TDQS_T)
DDR4_DQ0: U21.A19(D1_MDQ00) U37.C2(DQ0)
DDR4_DQ1: U21.C20(D1_MDQ01) U37.B7(DQ1)
DDR4_DQ2: U21.C23(D1_MDQ02) U37.D3(DQ2)
DDR4_DQ3: U21.D23(D1_MDQ03) U37.D7(DQ3)
DDR4_DQ4: U21.B19(D1_MDQ04) U37.D2(DQ4/NC)
DDR4_DQ5: U21.A20(D1_MDQ05) U37.D8(DQ5/NC)
DDR4_DQ6: U21.B23(D1_MDQ06) U37.E3(DQ6/NC)
DDR4_DQ7: U21.D22(D1_MDQ07) U37.E7(DQ7/NC)
DDR4_DQ8: U21.C21(D1_MDQ08) U36.C2(DQ0)
DDR4_DQ9: U21.E20(D1_MDQ09) U36.B7(DQ1)
DDR4_DQ10: U21.H21(D1_MDQ10) U36.D3(DQ2)
DDR4_DQ11: U21.J21(D1_MDQ11) U36.D7(DQ3)
DDR4_DQ12: U21.D19(D1_MDQ12) U36.D2(DQ4/NC)
DDR4_DQ13: U21.D21(D1_MDQ13) U36.D8(DQ5/NC)
DDR4_DQ14: U21.G20(D1_MDQ14) U36.E3(DQ6/NC)
DDR4_DQ15: U21.J20(D1_MDQ15) U36.E7(DQ7/NC)
DDR4_DQ16: U21.F22(D1_MDQ16) U35.C2(DQ0)
DDR4_DQ17: U21.G23(D1_MDQ17) U35.B7(DQ1)
DDR4_DQ18: U21.K23(D1_MDQ18) U35.D3(DQ2)
DDR4_DQ19: U21.M22(D1_MDQ19) U35.D7(DQ3)
DDR4_DQ20: U21.E23(D1_MDQ20) U35.D2(DQ4/NC)
DDR4_DQ21: U21.F23(D1_MDQ21) U35.D8(DQ5/NC)
DDR4_DQ22: U21.K22(D1_MDQ22) U35.E3(DQ6/NC)
DDR4_DQ23: U21.L23(D1_MDQ23) U35.E7(DQ7/NC)
DDR4_DQ24: U21.K21(D1_MDQ24) U34.C2(DQ0)
DDR4_DQ25: U21.L21(D1_MDQ25) U34.B7(DQ1)
DDR4_DQ26: U21.N21(D1_MDQ26) U34.D3(DQ2)
DDR4_DQ27: U21.P21(D1_MDQ27) U34.D7(DQ3)
DDR4_DQ28: U21.K19(D1_MDQ28) U34.D2(DQ4/NC)
DDR4_DQ29: U21.L19(D1_MDQ29) U34.D8(DQ5/NC)
DDR4_DQ30: U21.N20(D1_MDQ30) U34.E3(DQ6/NC)
DDR4_DQ31: U21.N19(D1_MDQ31) U34.E7(DQ7/NC)
DDR4_DQS0: U21.B22(D1_MDQS0) U37.C3(DQS_T)
DDR4_DQS0_n: U21.B21(~{D1_MDQS0}) U37.B3(DQS_C)
DDR4_DQS1: U21.G21(D1_MDQS1) U36.C3(DQS_T)
DDR4_DQS1_n: U21.F21(~{D1_MDQS1}) U36.B3(DQS_C)
DDR4_DQS2: U21.J23(D1_MDQS2) U35.C3(DQS_T)
DDR4_DQS2_n: U21.H23(~{D1_MDQS2}) U35.B3(DQS_C)
DDR4_DQS3: U21.M19(D1_MDQS3) U34.C3(DQS_T)
DDR4_DQS3_n: U21.M20(~{D1_MDQS3}) U34.B3(DQS_C)
DDR4_MCK0: R379.2 U21.W22(D1_MCK0) U34.F7(CK_T) U35.F7(CK_T) U36.F7(CK_T) U37.F7(CK_T)
DDR4_MCK0_n: R381.1 U21.W23(~{D1_MCK0}) U34.F8(CK_C) U35.F8(CK_C) U36.F8(CK_C) U37.F8(CK_C)
DDR4_MCKE0: R181.2 U21.R20(D1_MCKE0) U34.G3(CKE) U35.G3(CKE) U36.G3(CKE) U37.G3(CKE)
DDR4_MCKE1: R377.2 U21.U18(D1_MCKE1) U34.G2(C0/CKE1) U35.G2(C0/CKE1) U36.G2(C0/CKE1) U37.G2(C0/CKE1)
DDR4_ODT0: R375.2 U21.W19(D1_MODT0) U34.F3(ODT) U35.F3(ODT) U36.F3(ODT) U37.F3(ODT)
DDR4_ODT1: R166.2 U21.AC20(D1_MODT1) U34.F2(C2/ODT1) U35.F2(C2/ODT1) U36.F2(C2/ODT1) U37.F2(C2/ODT1)
DDR4_PAR: R387.2 U21.U22(D1_MAPAR_OUT) U34.N3(PAR) U35.N3(PAR) U36.N3(PAR) U37.N3(PAR)
DDR4_PAR_ERR: R390.2 U21.W21(~{D1_MAPAR_ERR}) U34.L9(~{ALERT}) U35.L9(~{ALERT}) U36.L9(~{ALERT}) U37.L9(~{ALERT})
DDR4_RAS: R169.2 U21.AC18(~{D1_MRAS}) U34.H8(~{RAS}/A16) U35.H8(~{RAS}/A16) U36.H8(~{RAS}/A16) U37.H8(~{RAS}/A16)
DDR4_VDD: C110.1 C111.1 C460.1 C472.1 C473.1 C475.1 C476.1 C479.1 C482.1 C489.1 C490.1 C492.1 C493.1 C494.1 C495.1 C496.1 C497.1 C498.1 C499.1 C504.1 C505.1 C506.1 C507.1 C508.1 C509.1 C510.1 C511.1 C512.1 C513.1 C514.1 C515.1 C516.1 C517.1 C518.1 C519.1 C520.1 C521.1 C522.1 C523.1 C526.1 C528.1 C530.1 C531.1 C532.1 C533.1 C535.1 C536.1 C537.1 C538.1 C539.1 C540.1 C541.1 C542.1 C552.1 C553.1 C554.1 C555.1 C569.1 C571.1 C572.1 C573.1 C574.1 C584.2 C585.2 C586.2 C587.2 C588.2 C589.2 C591.2 R343.1 R390.1 U34.A1(VDD1) U34.B2(VDDQ1) U34.B8(VDDQ2) U34.C1(VDDQ3) U34.C7(VDD2) U34.C9(VDDQ4) U34.E2(VDDQ5) U34.E8(VDDQ6) U34.F1(VDD3) U34.F9(VDD4) U34.H1(VDD5) U34.J9(VDD6) U34.M1(VDD7) U34.N9(VDD8) U35.A1(VDD1) U35.B2(VDDQ1) U35.B8(VDDQ2) U35.C1(VDDQ3) U35.C7(VDD2) U35.C9(VDDQ4) U35.E2(VDDQ5) U35.E8(VDDQ6) U35.F1(VDD3) U35.F9(VDD4) U35.H1(VDD5) U35.J9(VDD6) U35.M1(VDD7) U35.N9(VDD8) U36.A1(VDD1) U36.B2(VDDQ1) U36.B8(VDDQ2) U36.C1(VDDQ3) U36.C7(VDD2) U36.C9(VDDQ4) U36.E2(VDDQ5) U36.E8(VDDQ6) U36.F1(VDD3) U36.F9(VDD4) U36.H1(VDD5) U36.J9(VDD6) U36.M1(VDD7) U36.N9(VDD8) U37.A1(VDD1) U37.B2(VDDQ1) U37.B8(VDDQ2) U37.C1(VDDQ3) U37.C7(VDD2) U37.C9(VDDQ4) U37.E2(VDDQ5) U37.E8(VDDQ6) U37.F1(VDD3) U37.F9(VDD4) U37.H1(VDD5) U37.J9(VDD6) U37.M1(VDD7) U37.N9(VDD8) ; also on sheet 11 24
DDR4_VTT: C119.1 C120.1 C121.1 C123.1 C128.1 C131.1 C134.1 C135.1 C137.1 C144.1 C146.1 C148.1 C150.1 C151.1 C156.1 C159.1 C160.1 C161.1 C162.1 C166.1 C485.1 C486.1 C487.1 C584.1 C585.1 C586.1 C587.1 C588.1 C589.1 C591.1 C593.1 C594.1 C595.1 C599.1 C600.1 C605.1 C606.1 R166.1 R168.1 R169.1 R170.1 R171.1 R173.1 R174.1 R175.1 R176.1 R177.1 R178.1 R180.1 R181.1 R182.1 R183.1 R375.1 R376.1 R377.1 R378.1 R380.1 R382.1 R383.1 R384.1 R385.1 R386.1 R387.1 R388.1 R389.1 R391.1 ; also on sheet 24
eMMC_CLK: U32.2(I0A) U39.M6(CLK)
eMMC_CMD: U32.5(I0B) U39.M5(CMD)
eMMC_D0: U32.11(I0C) U39.A3(DAT0)
eMMC_D1: U32.14(I0D) U39.A4(DAT1)
eMMC_D2: U33.2(I0A) U39.A5(DAT2)
eMMC_D3: U33.5(I0B) U39.B2(DAT3)
eMMC_RST: Q13.3(COLLECTOR) R184.1 U39.K5(~{RST})
eMMC_SEL_n: Q12.3(COLLECTOR) R172.1 U32.1(S) U33.1(S)
EVDD: C113.1 C142.2 C149.1 C152.1 J16.4(VDD) R157.1 R158.1 R159.1 R160.1 R161.1 R162.1 R179.2 R184.2 U39.C6(VCCQ1) U39.M4(VCCQ3) U39.N4(VCCQ5) U39.P3(VCCQ4) U39.P5(VCCQ2) ; also on sheet 11 20
GPIO1_14_eMMC_SEL_n: Q12.2(EMITTER) Q29.2(EMITTER) Q30.2(EMITTER) SW3.3 ; also on sheet 8
IFC_A0: U20.31(A0) U25.23(2Q8)
IFC_A1: U20.26(A1) U25.22(2Q7)
IFC_A2: U20.25(A2) U25.20(2Q6)
IFC_A3: U20.24(A3) U25.19(2Q5)
IFC_A4: U20.23(A4) U25.17(2Q4)
IFC_A5: U20.22(A5) U25.16(2Q3)
IFC_A6: U20.21(A6) U25.14(2Q2)
IFC_A7: U20.20(A7) U25.13(2Q1)
IFC_A8: U20.10(A8) U25.12(1Q8)
IFC_A9: U20.9(A9) U25.11(1Q7)
IFC_A10: U20.8(A10) U25.9(1Q6)
IFC_A11: U20.7(A11) U25.8(1Q5)
IFC_A12: U20.6(A12) U25.6(1Q4)
IFC_A13: U20.5(A13) U25.5(1Q3)
IFC_A14: U20.4(A14) U25.3(1Q2)
IFC_A15: U20.3(A15) U25.2(1Q1)
IFC_A16: R299.1 SW2.5 U20.54(A16) U21.C7(IFC_A16)
IFC_A17: R292.1 SW2.6 U20.19(A17) U21.D7(IFC_A17)
IFC_A18: R304.1 SW2.3 U20.18(A18) U21.C8(IFC_A18)
IFC_A19: R302.1 SW2.4 U20.11(A19) U21.D8(IFC_A19)
IFC_A20: R308.1 U20.12(A20) U21.C9(IFC_A20)
IFC_A21: R315.2 U20.15(A21) U21.D9(IFC_A21/CFG_DRAM_TYPE)
IFC_A22: U20.2(A22) U21.C10(IFC_A22)
IFC_A23: U21.D10(IFC_A23) U27.1(A)
IFC_A23_INVERT: R140.2 SW3.7 U27.2(B) ; also on sheet 13
IFC_A24: U21.C11(IFC_A24) U24.1(A)
IFC_A24_INVERT: R138.2 SW3.6 U24.2(B) ; also on sheet 13
IFC_A25: R467.1 U21.D11(IFC_A25/GPIO2_25/~{IFC_WP1}/~{IFC_CS4}) U23.1(A)
IFC_A25_INVERT: R135.2 SW3.5 U23.2(B) ; also on sheet 13
IFC_A26: R468.1 U21.C12(IFC_A26/GPIO2_26/~{IFC_WP2}/~{IFC_CS5})
IFC_AD0: U16.J8(I/O7) U20.35(DQ0) U21.B6(IFC_AD00/CFG_GPINPUT0) U25.26(2D8)
IFC_AD1: U16.K7(I/O6) U20.37(DQ1) U21.A6(IFC_AD01/CFG_GPINPUT1) U25.27(2D7)
IFC_AD2: U16.J7(I/O5) U20.39(DQ2) U21.A7(IFC_AD02/CFG_GPINPUT2) U25.29(2D6)
IFC_AD3: U16.K6(I/O4) U20.41(DQ3) U21.B8(IFC_AD03/CFG_GPINPUT3) U25.30(2D5)
IFC_AD4: U16.K5(I/O3) U20.44(DQ4) U21.A8(IFC_AD04/CFG_GPINPUT4) U25.32(2D4)
IFC_AD5: U16.K4(I/O2) U20.46(DQ5) U21.B9(IFC_AD05/CFG_GPINPUT5) U25.33(2D3)
IFC_AD6: U16.J4(I/O1) U20.48(DQ6) U21.A9(IFC_AD06/CFG_GPINPUT6) U25.35(2D2)
IFC_AD7: U16.H4(I/O0) U20.50(DQ7) U21.A10(IFC_AD07/CFG_GPINPUT7) U25.36(2D1)
IFC_AD8: R245.2 SW1.1 U20.36(DQ8) U21.B11(IFC_AD08/CFG_RCW_SRC0) U25.37(1D8)
IFC_AD9: R251.2 SW1.2 U20.38(DQ9) U21.A11(IFC_AD09/CFG_RCW_SRC1) U25.38(1D7)
IFC_AD10: R253.2 SW1.3 U20.40(DQ10) U21.B12(IFC_AD10/CFG_RCW_SRC2) U25.40(1D6)
IFC_AD11: R255.2 SW1.4 U20.42(DQ11) U21.A12(IFC_AD11/CFG_RCW_SRC3) U25.41(1D5)
IFC_AD12: R257.2 SW1.5 U20.45(DQ12) U21.A13(IFC_AD12/CFG_RCW_SRC4) U25.43(1D4)
IFC_AD13: R262.2 SW1.6 U20.47(DQ13) U21.B14(IFC_AD13/CFG_RCW_SRC5) U25.44(1D3)
IFC_AD14: R268.2 SW1.7 U20.49(DQ14) U21.A14(IFC_AD14/CFG_RCW_SRC6) U25.46(1D2)
IFC_AD15: R276.2 SW1.8 U20.51(DQ15) U21.B15(IFC_AD15/CFG_RCW_SRC7) U25.47(1D1)
IFC_AVD: R321.2 SW2.8 U16.C4(ALE) U21.C15(IFC_AVD) U25.25(2LE) U25.48(1LE)
IFC_CLE: SW2.1 U16.D5(CLE) U21.C16(CFG_RCW_SRC8/IFC_CLE)
IFC_CS0: R317.1 U15.4(YA) U21.F13(~{IFC_CS0})
IFC_CS1: R319.1 U15.7(YB) U21.E14(GPIO2_10/~{IFC_CS1})
IFC_OE_n: R324.2 SW3.1 U16.D4(~{RE}) U20.34(~{OE}) U21.D15(~{IFC_OE})
IFC_RB0: R314.1 U15.11(I0C) U15.13(I1D) U21.F12(~{IFC_RB0})
IFC_RB1: R312.1 U15.10(I1C) U15.14(I0D) U21.E11(~{IFC_RB1})
IFC_TE: SW2.2 U21.A15(CFG_IFC_TE/IFC_TE)
IFC_WE_n: R310.2 R402.1 U16.C7(~{WE}) U20.13(~{WE}) U21.F11(CFG_ENG_USE0/~{IFC_WE0})
IFC_WP_n: SW3.2 U21.D16(~{IFC_WP0})
NAND_BOOT_SEL: R291.2 SW3.4 U15.1(S)
NAND_CS: U15.3(I1A) U15.5(I0B) U16.C6(~{CE})
NAND_RB: U15.12(YD) U16.C8(R/~{B})
NOR_CS: U15.2(I0A) U15.6(I1B) U20.32(~{CE})
NOR_RB: U15.9(YC) U20.17(RY/~{BY})
RESET: Q13.2(EMITTER) ; also on sheet 8 14 15 18 21
SD_CLK: J16.5(CLK) U30.1(P1) U30.8(NC8) U32.3(I1A)
SD_CMD: J16.2(CMD) U30.2(P2) U30.7(NC7) U32.6(I1B)
SD_D0: J16.7(DAT0) U30.3(P3) U30.6(NC6) U32.10(I1C)
SD_D1: J16.8(DAT1) U30.4(P4) U30.5(NC5) U32.13(I1D)
SD_D2: J16.9(DAT2) U31.1(P1) U31.8(NC8) U33.3(I1A)
SD_D3: J16.1(DAT3) U31.2(P2) U31.7(NC7) U33.6(I1B)
SDHC_CD_n: J16.3A(~{CD}) Q29.3(COLLECTOR) R156.1 U21.H3(~{SDHC_CD}/GPIO4_24/IIC3_SCL) U31.3(P3) U31.6(NC6)
SDHC_CLK: R160.2 R282.1 U32.4(YA)
SDHC_CMD: R159.2 U21.J2(SDHC_CMD/GPIO2_04/~{DMA1_DREQ0}) U32.7(YB)
SDHC_D0: R158.2 U21.J1(SDHC_DAT0/GPIO2_05/~{DMA1_DACK0}) U32.9(YC)
SDHC_D1: R157.2 U21.K2(SDHC_DAT1/GPIO2_06/~{DMA1_DDONE0}) U32.12(YD)
SDHC_D2: R162.2 U21.K1(SDHC_DAT2/GPIO2_07/~{DMA2_DREQ0}) U33.4(YA)
SDHC_D3: R161.2 U21.L1(SDHC_DAT3/GPIO2_08/~{DMA2_DACK0}) U33.7(YB)
SDHC_WP_n: J16.10(WP) Q30.3(COLLECTOR) R155.1 U21.H4(SDHC_WP/GPIO4_25/IIC3_SDA) U31.4(P4) U31.5(NC5)
SPI_CLK: R99.2 U14.16(SCK)
SPI_CS: R238.1 U14.7(~{CS}) U21.J4(SDHC_DAT4/GPIO2_00/~{SPI_CS0})
SPI_MISO: U14.8(SO/IO1) U21.M3(SPI_MISO)
SPI_MOSI: U14.15(SI/IO0) U21.M4(SPI_MOSI)
TEST_SEL_N: SW3.8 ; also on sheet 8
N24325827: R342.2 U21.V23(D1_MDIC0)
N24331550: R371.2 U37.B9(ZQ)
N24334551: R339.2 U21.M23(D1_MECC0)
N24334558: R338.2 U21.N23(D1_MECC1)
N24334565: R340.2 U21.R22(D1_MECC2)
N24334572: R341.2 U21.T23(D1_MECC3)
N24340384: R372.2 U36.B9(ZQ)
N24342556: R374.2 U35.B9(ZQ)
N24344964: R373.2 U34.B9(ZQ)
N24364084: R301.1 U20.16(~{WP})
N24368311: R243.1 U16.C3(~{WP})
N24370219: R239.1 U14.9(~{WP}/IO2)
N24370226: R237.1 U14.1(~{HOLD}/IO3)
N24371075: R282.2 U21.H1(SDHC_CLK/GPIO2_09/~{DMA2_DDONE0})
N24377296: C140.1 C141.1 U39.C2(VDDI)
N24421074: R244.2 SW1.16
N24421076: R250.2 SW1.15
N24421078: R252.2 SW1.14
N24421080: R254.2 SW1.13
N24421082: R256.2 SW1.12
N24421084: R261.2 SW1.11
N24421086: R267.2 SW1.10
N24421088: R275.2 SW1.9
N24421090: R293.2 SW2.16
N24421092: R300.2 SW2.15
N24421094: R303.2 SW2.14
N24421096: R307.2 SW2.13
N24421098: R313.2 SW2.11
N24421100: R311.2 SW2.12
N24421104: R318.2 SW2.9
N24426897: R325.1 U21.C14(GPIO2_15/~{IFC_PERR})
N24433996: R130.2 SW3.16
N24433998: R131.2 SW3.15
N24434000: R132.1 SW3.14
N24434027: R133.1 SW3.13
N24434063: R136.1 SW3.12
N24434090: R139.1 SW3.11
N24434117: R141.1 SW3.10
N24658856: R343.2 U21.Y23(D1_MDIC1)
N24873583: Q13.1(BASE) R179.1
N24892373: Q12.1(BASE) R165.2
N25019525: C535.2 R379.1 R381.2
N25263474: R354.2 U21.M17(D1_MVREF)
N25435604: R99.1 U21.L3(SPI_CLK)
N25495882: TP15.1(Pin1) U21.A17(IFC_CLK0)
N25614619: TP16.1(Pin1) U21.B17(IFC_CLK1)
N25614638: TP13.1(Pin1) U21.C13(IFC_NDDDR_CLK)
N25614641: TP31.1(Pin1) U21.E13(IFC_NDDQS)
N25614652: TP32.1(Pin1) U21.D12(IFC_A27/GPIO2_27/~{IFC_WP3}/~{IFC_CS6})
N25614663: TP43.1(Pin1) U21.P17(D1_TPA)
N26207914: TP45.1(Pin1) U21.F14(GPIO2_11/~{IFC_CS2})
N26207917: TP46.1(Pin1) U21.F15(GPIO2_12/~{IFC_CS3})
N26208803: TP47.1(Pin1) U21.J3(SDHC_CMD_DIR/SDHC_DAT5/GPIO2_01/~{SPI_CS1})
N26208818: TP48.1(Pin1) U21.K4(SDHC_DAT0_DIR/SDHC_DAT6/GPIO2_02/~{SPI_CS2})
N26208833: TP49.1(Pin1) U21.K3(SDHC_DAT123_DIR/SDHC_CLK_SYNC_OUT/SDHC_DAT7/GPIO2_03/~{SPI_CS3})
N26623594: TP55.1(Pin1) U21.D14(GPIO2_13/IFC_PAR0)
N26623597: TP56.1(Pin1) U21.D13(GPIO2_14/IFC_PAR1)
N26816813: Q29.1(BASE) R460.2
N26817083: Q30.1(BASE) R461.1

Not connected (* = marked no-connect by the designer): SW2 7* 10*; U14 4(DNU1)* 5(DNU2)* 6(RFU)* 11(DNU3)* 12(DNU4)* 13(NC)*; U16 A1(NC)* A2(NC)* A9(NC)* A10(NC)* B1(NC)* B9(NC)* B10(NC)* D6(NC)* D7(NC)* D8(NC)* E3(NC)* E4(NC)* E5(NC)* E6(NC)* E7(NC)* E8(NC)* F3(NC)* F4(NC)* F5(NC)* F6(NC)* F8(NC)* G3(NC)* G5(NC)* G6(NC)* G7(NC)* G8(NC)* H3(NC)* H5(NC)* H6(NC)* H7(NC)* J3(NC)* J5(NC)* L1(NC)* L2(NC)* L9(NC)* L10(NC)* M1(NC)* M2(NC)* M9(NC)* M10(NC)*; U20 27(RFU1)* 28(DNU)* 30(RFU2)* 53(RFU3)*; U21 A16(IFC_BCTL)* AA22(D1_MCK1)* AA23(~{D1_MCK1})* AC19(~{D1_MCS3})* N22(D1_MDM8)* P23(~{D1_MDQS8})* R23(D1_MDQS8)* V17(~{D1_MCS2})*; U33 9(YC)* 10(I1C)* 11(I0C)* 12(YD)* 13(I1D)* 14(I0D)*; U34 A3(NF/TDQS_C)* G9(RFU/TEN)* N7(A17/NC)*; U35 A3(NF/TDQS_C)* G9(RFU/TEN)* N7(A17/NC)*; U36 A3(NF/TDQS_C)* G9(RFU/TEN)* N7(A17/NC)*; U37 A3(NF/TDQS_C)* G9(RFU/TEN)* N7(A17/NC)*; U39 A1(NC)* A2(NC)* A6(RFU1)* A7(RFU2)* A8(NC)* A9(NC)* A10(NC)* A11(NC)* A12(NC)* A13(NC)* A14(NC)* B1(NC)* B3(DAT4)* B4(DAT5)* B5(DAT6)* B6(DAT7)* B7(NC)* B8(NC)* B9(NC)* B10(NC)* B11(NC)* B12(NC)* B13(NC)* B14(NC)* C1(NC)* C3(NC)* C5(RFU3)* C7(NC)* C8(NC)* C9(NC)* C10(NC)* C11(NC)* C12(NC)* C13(NC)* C14(NC)* D1(NC)* D2(NC)* D3(NC)* D4(NC)* D12(NC)* D13(NC)* D14(NC)* E1(NC)* E2(NC)* E3(NC)* E5(RFU5)* E8(RFU6)* E9(RFU7)* E10(RFU4)* E12(NC)* E13(NC)* E14(NC)* F1(NC)* F2(NC)* F3(NC)* F10(RFU8)* F12(NC)* F13(NC)* F14(NC)* G1(NC)* G2(NC)* G3(RFU10)* G10(RFU9)* G12(NC)* G13(NC)* G14(NC)* H1(NC)* H2(NC)* H3(NC)* H5(RFU11)* H12(NC)* H13(NC)* H14(NC)* J1(NC)* J2(NC)* J3(NC)* J5(RFU12)* J12(NC)* J13(NC)* J14(NC)* K1(NC)* K2(NC)* K3(NC)* K6(RFU14)* K7(RFU15)* K10(RFU13)* K12(NC)* K13(NC)* K14(NC)* L1(NC)* L2(NC)* L3(NC)* L12(NC)* L13(NC)* L14(NC)* M1(NC)* M2(NC)* M3(NC)* M7(NC)* M8(NC)* M9(NC)* M10(NC)* M11(NC)* M12(NC)* M13(NC)* M14(NC)* N1(NC)* N3(NC)* N6(NC)* N7(NC)* N8(NC)* N9(NC)* N10(NC)* N11(NC)* N12(NC)* N13(NC)* N14(NC)* P1(NC)* P2(NC)* P7(RFU17)* P8(NC)* P9(NC)* P10(RFU16)* P11(NC)* P12(NC)* P13(NC)* P14(NC)*

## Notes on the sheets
sheet 1
- Table of Contents
- 2
- Systen Block Diagram
- 3
- Power Block Diagram
- 4
- System Clock Diagram
- 5
- DDR4
- 6
- IFC
- Rev
- Data
- Revision History
- PCB Version
- 7
- SPI&SDHC
- 8
- System
- A
- A
- 02/12/2014
- Initial Version
- 9
- EC&SerDes
- 10
- USB
- Assign a different agile part number
  for U38 PMIC, as a new image programmed
  to the internal OTROM
- 11
- T1023 PWR
- A1
- 02/12/2014
- A
- 12
- T1023 GND
- 13
- UART&I2C
- 14
- EC1 PHY RGMII
- 1. Correct DDR data line cross between nibbles issue
  2. Replace GPIO2_01,02,03,11&12 with GPIO1_14,18,16,
     20&22
  3. Connect GPIO1_14 to SW4.3
  4. Change U15,U18 VCC to 3.3V as the new GPIO
     power is 3.3V, move the original caps to the NOR
     1.8V and add new two caps as DNP to the 3.3V
  5. Change the SW4 pull high voltage to 3.3V as
     the new GPIO power is 3.3V
  6. Connect the U17,U42 address pin to 3.3V
  7. Populate R107,R109
  8. Set SW4.2 to on
  9. Use POR reset to RTL8211 PHY
  10. DNP R164
  11. Solder Silicon
  12. Change SW2 setting to SPI boot
- 15
- SGMII PHY 1G
- 16
- AQR105 2.5G
- 17
- AQR105 POWER
- B
- 23/12/2014
- 18
- PCIe
- 19
- CLOCK
- B
- 20
- VR500(1V5/1V8/1V2/1V35/2V5)
- 21
- V85/2V1/1V2/5V0
- 22
- CORE&S1VDD&3V3
- 23
- 12V POWER&RESET
- 24
- PoE
- 1. P6: disconnect IFC_WE_n to SW4.1,add R402 from
  IFC_WE_n to ground
  2. P6: connect IFC_OE_n to SW4.1
  3. P6: connect IFC_WP_n to SW4.2
  4. P6: change R132 to 330ohm
  5. P6: Use IDTQS3VH257PA to switch CS and RB signal
  6. P6: reconnect NOR flash use small endian connection
  7. P7: change R282 to 49.9ohm for EMI
  8. P7: change R155,R156 to 330ohm;add Q29,Q30 for eMMC
  detect and write protection
  9. P8: disconnect GPIO1_18 to SW4.4, add a test point
  10. P9: populate C331 for EMI
  11. P14: populate C45, change C42 to 22PF and populate,
  change R50 to 33ohm for EMI
  12. P14: add R404 39ohm to divide the 125M clock to 1.8V
  13. P14: populate C22,C24 for EMI,delete R41 for EMI
  14. P15: populate C20,C23 for EMI
  15. P16: DNP J7
  16. P19: Delete  R103 for EMI;DNP J12
  17. P20: DNP J14
  18. P21: add C611 fix LDO out 0.5V without enabling issue
  19. P22: connect J9.3 to GND
  20. P6: Disconnect GPIO2_13,GPIO2_14 to LEDs, add test
  point to GPIOs.
  21. P18. Add LEDs to PCIe slot pin44
  22. P9. connect GPIO3_0~GPIO3_3as PCIE wake up and clkreq
  use GPIO3_4 and GPIO3_5 as board version
  23.P18. Connect PCIE pin 39,41 to 3.3V
  24.P18. Add DCDC for WiFi card CUS239,CUS260 PA
  25.P8. Disconnect IRQ4 to VR500, connect IRQ4 to PCIE wake
  26.P20.DNP L22 to disconnect 1V5 to PCIE
  27.P23.delete R12,R18
  28.P8.delete J15,set JTAG power to 3.3V
  29.Change the board part number to X-T1023RDB-PC
  30.P18, replace PCIe slot with low height connector , 1.6mm stand off
  31.Replace the current sense IC
  32.Add jumper to turn on/off DCDC for PoE test
  33.P6 Delete C448
  34.Add 2.5G port PoE support
  35.P6 connect IFC_A21 to R315 directly for DDR4 type
  36.P16 change R280 pull high to 1.2V
  37.P13 add I2C expander for bank selecting
  38.P6, add pull height resister to A25 and A26, delete A26
  test point
  39.P18, add DCDC for each card PA
- C
- 13/05/2015
- C1
- X-T1023RDB-PC
sheet 2
- SYSTEM BLOCK DIAGRAM
sheet 5
- full or half driver
  strength calibration
- D1_MVREF to
  Ground on DDR4
  mode
- NOTES:
  1:DQ swap across
  nibbles is not allowed
  2:DQ0 is used to enable
  Per-DRAM Addressability,
  so DQ0 swap is also not
  allowed
sheet 6
- 512MX8bit 4bit ECC
- SW1[1:8]ONONONOFFONOFFOFFOFF
  SW2[1]OFF     NOR BOOT
- cfg_rcw_src0
- cfg_rcw_src1
- cfg_rcw_src2
- cfg_rcw_src3
- cfg_rcw_src4
- cfg_rcw_src5
- cfg_rcw_src6
- cfg_rcw_src7
- cfg_rcw_src[0:8]
  0_0010_1111: NOR FLASH BOOT   Default
  0_0100_0000: SD CARD BOOT
  0_0100_0101: SPI BOOT
  1_0000_0100: NAND FLASH BOOT
- cfg_eng_use1
- cfg_eng_use0
- cfg_eng_use2
- DIFF SYSCLK
- 0:TE Asset High;
  1:TE assert low
- cfg_rcw_src8
- KEEP HIGH DURING POR
- cfg_ifc_te
- cfg_pll_config_sel_b
- NOR:0;NAND:1
- cfg_por_ainit
- cfg_svr0
- cfg_svr1
- cfg_dram_type
- cfg_rsp_dis
- Dual Core : 1 Signle Core: 0
- SW2[1:8]OFFOFFOFFOFFOFFOFFOFFOFF
- SW3[1:8]:OFFOFFOFFONONONONOFF
